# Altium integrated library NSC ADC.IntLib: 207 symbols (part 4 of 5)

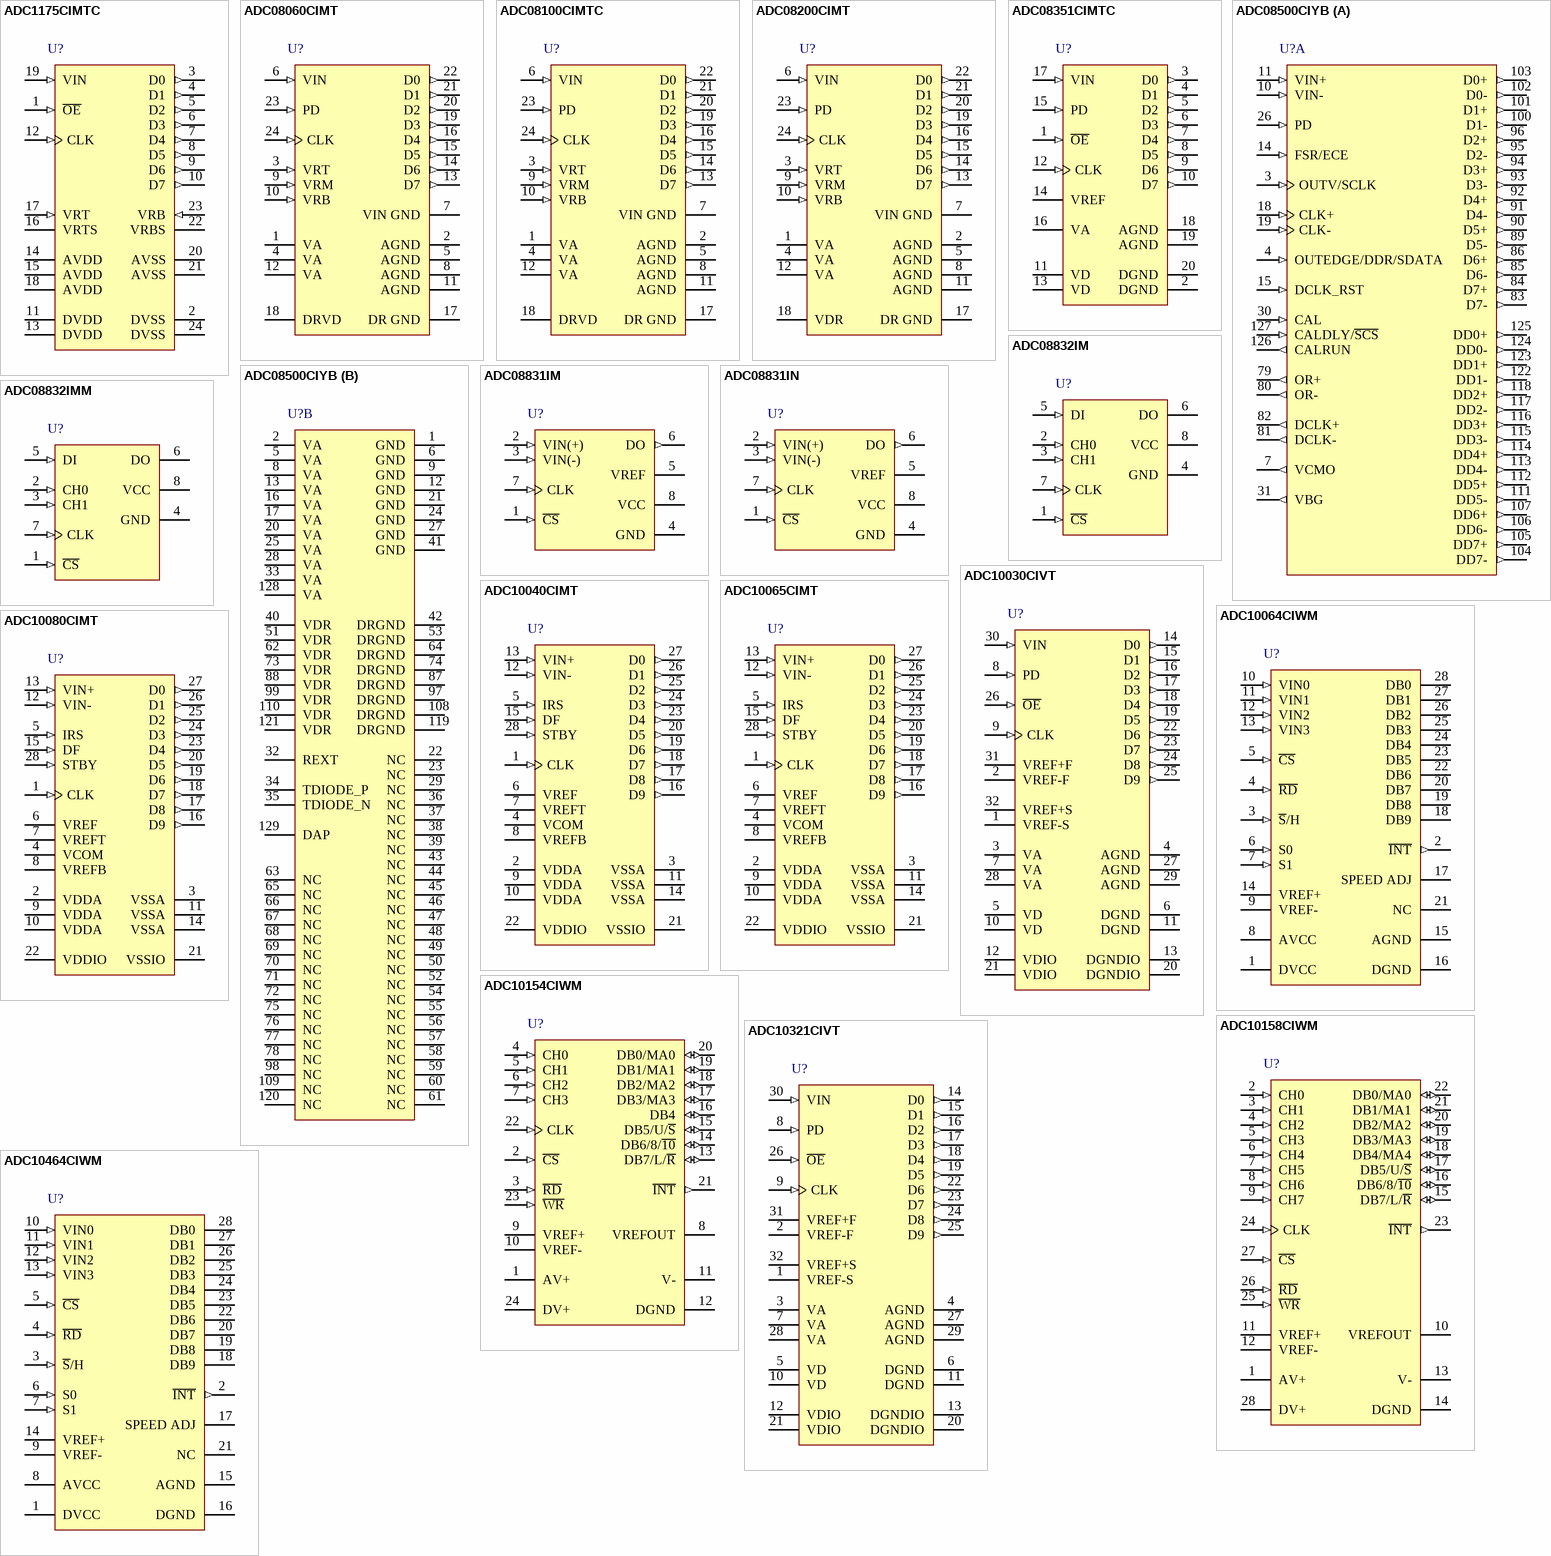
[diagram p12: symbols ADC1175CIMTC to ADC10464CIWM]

## ADC1175CIMTC
designator U?
8-Bit, 20MHz, 60mW A/D Converter; PartNumber: ADC1175CIMTC; Manufacturer: National Semiconductor; CompType: ADC IC; PackageTopMarking: NSUZXYTT*ADC1175*CIMTC; PowerWise: N
footprint MTC24_N (TSOP, 24-Leads, Body 7.8x4.4mm, Pitch 0.65mm, IPC Medium Density)
footprint MTC24_L (TSOP, 24-Leads, Body 7.8x4.4mm, Pitch 0.65mm, IPC High Density)
footprint MTC24_M (TSOP, 24-Leads, Body 7.8x4.4mm, Pitch 0.65mm, IPC Low Density)
pins: 1 ~{OE} (in), 2 DVSS (power), 3 D0 (out), 4 D1 (out), 5 D2 (out), 6 D3 (out), 7 D4 (out), 8 D5 (out), 9 D6 (out), 10 D7 (out), 11 DVDD (power), 12 CLK (in), 13 DVDD (power), 14 AVDD (power), 15 AVDD (power), 16 VRTS, 17 VRT (in), 18 AVDD (power), 19 VIN (in), 20 AVSS (power), 21 AVSS (power), 22 VRBS, 23 VRB (in), 24 DVSS (power)

## ADC08060CIMT
designator U?
8-Bit, 20 MSPS to 60 MSPS, 1.3 mW/MSPS A/D Converter with Internal Sample-and-Hold; PartNumber: ADC08060CIMT; Manufacturer: National Semiconductor; CompType: ADC IC; PackageTopMarking: NSUZXYTT*ADC08060*CIMT; PowerWise: N
footprint MTC24_N (TSOP, 24-Leads, Body 7.8x4.4mm, Pitch 0.65mm, IPC Medium Density)
footprint MTC24_L (TSOP, 24-Leads, Body 7.8x4.4mm, Pitch 0.65mm, IPC High Density)
footprint MTC24_M (TSOP, 24-Leads, Body 7.8x4.4mm, Pitch 0.65mm, IPC Low Density)
pins: 1 VA (power), 2 AGND (power), 3 VRT (in), 4 VA (power), 5 AGND (power), 6 VIN (in), 7 VIN GND (power), 8 AGND (power), 9 VRM (in), 10 VRB (in), 11 AGND (power), 12 VA (power), 13 D7 (out), 14 D6 (out), 15 D5 (out), 16 D4 (out), 17 DR GND (power), 18 DRVD (power), 19 D3 (out), 20 D2 (out), 21 D1 (out), 22 D0 (out), 23 PD (in), 24 CLK (in)

## ADC08100CIMTC
designator U?
8-Bit, 20 Msps to 100 Msps, 1.3 mW/Msps A/D Converter; PartNumber: ADC08100CIMTC; Manufacturer: National Semiconductor; CompType: ADC IC; PackageTopMarking: NSUZXYTT*ADC08100*CIMTC; PowerWise: N
footprint MTC24_N (TSOP, 24-Leads, Body 7.8x4.4mm, Pitch 0.65mm, IPC Medium Density)
footprint MTC24_L (TSOP, 24-Leads, Body 7.8x4.4mm, Pitch 0.65mm, IPC High Density)
footprint MTC24_M (TSOP, 24-Leads, Body 7.8x4.4mm, Pitch 0.65mm, IPC Low Density)
pins: 1 VA (power), 2 AGND (power), 3 VRT (in), 4 VA (power), 5 AGND (power), 6 VIN (in), 7 VIN GND (power), 8 AGND (power), 9 VRM (in), 10 VRB (in), 11 AGND (power), 12 VA (power), 13 D7 (out), 14 D6 (out), 15 D5 (out), 16 D4 (out), 17 DR GND (power), 18 DRVD (power), 19 D3 (out), 20 D2 (out), 21 D1 (out), 22 D0 (out), 23 PD (in), 24 CLK (in)

## ADC08200CIMT
designator U?
8-Bit, 20 Msps to 200 Msps, Low Power A/D Converter with Internal Sample-and-Hold; PartNumber: ADC08200CIMT; Manufacturer: National Semiconductor; CompType: ADC IC; PackageTopMarking: NSUZXYTT*ADC08200*CIMT; PowerWise: Y
footprint MTC24_N (TSOP, 24-Leads, Body 7.8x4.4mm, Pitch 0.65mm, IPC Medium Density)
footprint MTC24_L (TSOP, 24-Leads, Body 7.8x4.4mm, Pitch 0.65mm, IPC High Density)
footprint MTC24_M (TSOP, 24-Leads, Body 7.8x4.4mm, Pitch 0.65mm, IPC Low Density)
pins: 1 VA (power), 2 AGND (power), 3 VRT (in), 4 VA (power), 5 AGND (power), 6 VIN (in), 7 VIN GND (power), 8 AGND (power), 9 VRM (in), 10 VRB (in), 11 AGND (power), 12 VA (power), 13 D7 (out), 14 D6 (out), 15 D5 (out), 16 D4 (out), 17 DR GND (power), 18 VDR (power), 19 D3 (out), 20 D2 (out), 21 D1 (out), 22 D0 (out), 23 PD (in), 24 CLK (in)

## ADC08351CIMTC
designator U?
8-Bit, 42 MSPS, 40 mW A/D Converter; PartNumber: ADC08351CIMTC; Manufacturer: National Semiconductor; CompType: ADC IC; PackageTopMarking: NSUZXYTT*ADC08351*CIMTC
footprint MTC20_N (TSOP, 20-Leads, Body 6.5x4.4mm, Pitch 0.65mm, IPC Medium Density)
footprint MTC20_L (TSOP, 20-Leads, Body 6.5x4.4mm, Pitch 0.65mm, IPC High Density)
footprint MTC20_M (TSOP, 20-Leads, Body 6.5x4.4mm, Pitch 0.65mm, IPC Low Density)
pins: 1 ~{OE} (in), 2 DGND (power), 3 D0 (out), 4 D1 (out), 5 D2 (out), 6 D3 (out), 7 D4 (out), 8 D5 (out), 9 D6 (out), 10 D7 (out), 11 VD (power), 12 CLK (in), 13 VD (power), 14 VREF (power), 15 PD (in), 16 VA (power), 17 VIN (in), 18 AGND (power), 19 AGND (power), 20 DGND (power)

## ADC08500CIYB
designator U?
High Performance, Low Power, Dual 8-Bit, 500 MSPS A/D Converter; PartNumber: ADC08500CIYB; Manufacturer: National Semiconductor; CompType: ADC IC; PackageTopMarking: NSUZXYYTTE#*ADC08500CIYB; PowerWise: Y
footprint VNX128A_N (Thin QFP, 128-Leads, Body 20x20mm, Pitch 0.5mm, Exposed Pad, IPC Medium Density)
footprint VNX128A_L (Thin QFP, 128-Leads, Body 20x20mm, Pitch 0.5mm, Exposed Pad, IPC High Density)
footprint VNX128A_M (Thin QFP, 128-Leads, Body 20x20mm, Pitch 0.5mm, Exposed Pad, IPC Low Density)
part A pins: 3 OUTV/SCLK (in), 4 OUTEDGE/DDR/SDATA (in), 7 VCMO (out), 10 VIN- (in), 11 VIN+ (in), 14 FSR/ECE (in), 15 DCLK_RST (in), 18 CLK+ (in), 19 CLK- (in), 26 PD (in), 30 CAL (in), 31 VBG (out), 79 OR+ (out), 80 OR- (out), 81 DCLK- (out), 82 DCLK+ (out), 83 D7- (out), 84 D7+ (out), 85 D6- (out), 86 D6+ (out), 89 D5- (out), 90 D5+ (out), 91 D4- (out), 92 D4+ (out), 93 D3- (out), 94 D3+ (out), 95 D2- (out), 96 D2+ (out), 100 D1- (out), 101 D1+ (out), 102 D0- (out), 103 D0+ (out), 104 DD7- (out), 105 DD7+ (out), 106 DD6- (out), 107 DD6+ (out), 111 DD5- (out), 112 DD5+ (out), 113 DD4- (out), 114 DD4+ (out), 115 DD3- (out), 116 DD3+ (out), 117 DD2- (out), 118 DD2+ (out), 122 DD1- (out), 123 DD1+ (out), 124 DD0- (out), 125 DD0+ (out), 126 CALRUN (out), 127 CALDLY/~{SCS} (in)
part B pins: 1 GND (power), 2 VA (power), 5 VA (power), 6 GND (power), 8 VA (power), 9 GND (power), 12 GND (power), 13 VA (power), 16 VA (power), 17 VA (power), 20 VA (power), 21 GND (power), 22 NC, 23 NC, 24 GND (power), 25 VA (power), 27 GND (power), 28 VA (power), 29 NC, 32 REXT, 33 VA (power), 34 TDIODE_P, 35 TDIODE_N, 36 NC, 37 NC, 38 NC, 39 NC, 40 VDR (power), 41 GND (power), 42 DRGND (power), 43 NC, 44 NC, 45 NC, 46 NC, 47 NC, 48 NC, 49 NC, 50 NC, 51 VDR (power), 52 NC, 53 DRGND (power), 54 NC, 55 NC, 56 NC, 57 NC, 58 NC, 59 NC, 60 NC, 61 NC, 62 VDR (power), 63 NC, 64 DRGND (power), 65 NC, 66 NC, 67 NC, 68 NC, 69 NC, 70 NC, 71 NC, 72 NC, 73 VDR (power), 74 DRGND (power), 75 NC, 76 NC, 77 NC, 78 NC, 87 DRGND (power), 88 VDR (power), 97 DRGND (power), 98 NC, 99 VDR (power), 108 DRGND (power), 109 NC, 110 VDR (power), 119 DRGND (power), 120 NC, 121 VDR (power), 128 VA (power), 129 DAP (power)

## ADC08831IM
designator U?
8-Bit Serial I/O CMOS A/D Converters with Multiplexer and Sample/Hold Function; PartNumber: ADC08831IM; Manufacturer: National Semiconductor; CompType: ADC IC; PackageTopMarking: NSZXTT*08831*IM; PowerWise: N
footprint M08A_N (SOIC, 8-Leads, Body 4.9x3.9mm, Pitch 1.27mm, IPC Medium Density)
footprint M08A_L (SOIC, 8-Leads, Body 4.9x3.9mm, Pitch 1.27mm, IPC High Density)
footprint M08A_M (SOIC, 8-Leads, Body 4.9x3.9mm, Pitch 1.27mm, IPC Low Density)
pins: 1 ~{CS} (in), 2 VIN(+) (in), 3 VIN(-) (in), 4 GND (power), 5 VREF (power), 6 DO (out), 7 CLK (in), 8 VCC (power)

## ADC08831IN
designator U?
8-Bit Serial I/O CMOS A/D Converters with Multiplexer and Sample/Hold Function; PartNumber: ADC08831IN; Manufacturer: National Semiconductor; CompType: ADC IC; PackageTopMarking: NSUZXYTT*ADC08831*IN
footprint N08E (DIP, 8-Leads, Row Spacing 7.62mm, Pitch 2.54mm, Body 9.91x6.35mm)
pins: 1 ~{CS} (in), 2 VIN(+) (in), 3 VIN(-) (in), 4 GND (power), 5 VREF (power), 6 DO (out), 7 CLK (in), 8 VCC (power)

## ADC08832IM
designator U?
8-Bit Serial I/O CMOS A/D Converters with Multiplexer and Sample/Hold Function; PartNumber: ADC08832IM; Manufacturer: National Semiconductor; CompType: ADC IC; PackageTopMarking: NSZXTT*08832*IM; PowerWise: N
footprint M08A_N (SOIC, 8-Leads, Body 4.9x3.9mm, Pitch 1.27mm, IPC Medium Density)
footprint M08A_L (SOIC, 8-Leads, Body 4.9x3.9mm, Pitch 1.27mm, IPC High Density)
footprint M08A_M (SOIC, 8-Leads, Body 4.9x3.9mm, Pitch 1.27mm, IPC Low Density)
pins: 1 ~{CS} (in), 2 CH0 (in), 3 CH1 (in), 4 GND (power), 5 DI (in), 6 DO (hiz), 7 CLK (in), 8 VCC (power)

## ADC08832IMM
designator U?
8-Bit Serial I/O CMOS A/D Converters with Multiplexer and Sample/Hold Function; PartNumber: ADC08832IMM; Manufacturer: National Semiconductor; CompType: ADC IC; PackageTopMarking: ZXTT*8832; PowerWise: N
footprint MUA08A_N (TSOP, 8-Leads, Body 3x3mm, Pitch 0.65mm, IPC Medium Density)
footprint MUA08A_L (TSOP, 8-Leads, Body 3x3mm, Pitch 0.65mm, IPC High Density)
footprint MUA08A_M (TSOP, 8-Leads, Body 3x3mm, Pitch 0.65mm, IPC Low Density)
pins: 1 ~{CS} (in), 2 CH0 (in), 3 CH1 (in), 4 GND (power), 5 DI (in), 6 DO (hiz), 7 CLK (in), 8 VCC (power)

## ADC10030CIVT
designator U?
10-Bit, 30 MSPS, 125 mW A/D Converter with Internal Sample and Hold; PartNumber: ADC10030CIVT; Manufacturer: National Semiconductor; CompType: ADC IC; PackageTopMarking: NS2ZXYTT*ADC10030*CIVT
footprint VBE32A_N (Thin QFP, 32-Leads, Body 7x7mm, Pitch 0.8mm, IPC Medium Density)
footprint VBE32A_L (Thin QFP, 32-Leads, Body 7x7mm, Pitch 0.8mm, IPC High Density)
footprint VBE32A_M (Thin QFP, 32-Leads, Body 7x7mm, Pitch 0.8mm, IPC Low Density)
pins: 1 VREF-S (power), 2 VREF-F (power), 3 VA (power), 4 AGND (power), 5 VD (power), 6 DGND (power), 7 VA (power), 8 PD (in), 9 CLK (in), 10 VD (power), 11 DGND (power), 12 VDIO (power), 13 DGNDIO (power), 14 D0 (out), 15 D1 (out), 16 D2 (out), 17 D3 (out), 18 D4 (out), 19 D5 (out), 20 DGNDIO (power), 21 VDIO (power), 22 D6 (out), 23 D7 (out), 24 D8 (out), 25 D9 (out), 26 ~{OE} (in), 27 AGND (power), 28 VA (power), 29 AGND (power), 30 VIN (in), 31 VREF+F (power), 32 VREF+S (power)

## ADC10040CIMT
designator U?
10-Bit, 40 MSPS, 3V, 55.5 mW A/D Converter; PartNumber: ADC10040CIMT; Manufacturer: National Semiconductor; CompType: ADC IC; PackageTopMarking: NSUZXYTT*ADC10040*CIMT; PowerWise: Y
footprint MTC28_N (TSOP, 28-Leads, Body 9.7x4.4mm, Pitch 0.65mm, IPC Medium Density)
footprint MTC28_L (TSOP, 28-Leads, Body 9.7x4.4mm, Pitch 0.65mm, IPC High Density)
footprint MTC28_M (TSOP, 28-Leads, Body 9.7x4.4mm, Pitch 0.65mm, IPC Low Density)
pins: 1 CLK (in), 2 VDDA (power), 3 VSSA (power), 4 VCOM (power), 5 IRS (in), 6 VREF (power), 7 VREFT (power), 8 VREFB (power), 9 VDDA (power), 10 VDDA (power), 11 VSSA (power), 12 VIN- (in), 13 VIN+ (in), 14 VSSA (power), 15 DF (in), 16 D9 (out), 17 D8 (out), 18 D7 (out), 19 D6 (out), 20 D5 (out), 21 VSSIO (power), 22 VDDIO (power), 23 D4 (out), 24 D3 (out), 25 D2 (out), 26 D1 (out), 27 D0 (out), 28 STBY (in)

## ADC10064CIWM
designator U?
10-Bit 600 ns A/D Converter with Input Multiplexer and Sample/Hold; PartNumber: ADC10064CIWM; Manufacturer: National Semiconductor; CompType: ADC IC; PackageTopMarking: NSUZXYTT*ADC10064*CIWM; PowerWise: N
footprint M28B_N (SOIC, 28-Leads, Body 17.9x7.5mm, Pitch 1.27mm, IPC Medium Density)
footprint M28B_L (SOIC, 28-Leads, Body 17.9x7.5mm, Pitch 1.27mm, IPC High Density)
footprint M28B_M (SOIC, 28-Leads, Body 17.9x7.5mm, Pitch 1.27mm, IPC Low Density)
pins: 1 DVCC (power), 2 ~{INT} (out), 3 ~{S}/H (in), 4 ~{RD} (in), 5 ~{CS} (in), 6 S0 (in), 7 S1 (in), 8 AVCC (power), 9 VREF- (power), 10 VIN0 (in), 11 VIN1 (in), 12 VIN2 (in), 13 VIN3 (in), 14 VREF+ (power), 15 AGND (power), 16 DGND (power), 17 SPEED ADJ, 18 DB9 (hiz), 19 DB8 (hiz), 20 DB7 (hiz), 21 NC, 22 DB6 (hiz), 23 DB5 (hiz), 24 DB4 (hiz), 25 DB3 (hiz), 26 DB2 (hiz), 27 DB1 (hiz), 28 DB0 (hiz)

## ADC10065CIMT
designator U?
10-Bit 65 MSPS 3V A/D Converter; PartNumber: ADC10065CIMT; Manufacturer: National Semiconductor; CompType: ADC IC; PackageTopMarking: NSUZXYTT*ADC10065*CIMT; PowerWise: Y
footprint MTC28_N (TSOP, 28-Leads, Body 9.7x4.4mm, Pitch 0.65mm, IPC Medium Density)
footprint MTC28_L (TSOP, 28-Leads, Body 9.7x4.4mm, Pitch 0.65mm, IPC High Density)
footprint MTC28_M (TSOP, 28-Leads, Body 9.7x4.4mm, Pitch 0.65mm, IPC Low Density)
pins: 1 CLK (in), 2 VDDA (power), 3 VSSA (power), 4 VCOM (power), 5 IRS (in), 6 VREF (power), 7 VREFT (power), 8 VREFB (power), 9 VDDA (power), 10 VDDA (power), 11 VSSA (power), 12 VIN- (in), 13 VIN+ (in), 14 VSSA (power), 15 DF (in), 16 D9 (out), 17 D8 (out), 18 D7 (out), 19 D6 (out), 20 D5 (out), 21 VSSIO (power), 22 VDDIO (power), 23 D4 (out), 24 D3 (out), 25 D2 (out), 26 D1 (out), 27 D0 (out), 28 STBY (in)

## ADC10080CIMT
designator U?
10-Bit, 80 MSPS, 3V, 78.6 mW A/D Converter; PartNumber: ADC10080CIMT; Manufacturer: National Semiconductor; CompType: ADC IC; PackageTopMarking: NSUZXYTT*ADC10080*CIMT; PowerWise: Y
footprint MTC28_N (TSOP, 28-Leads, Body 9.7x4.4mm, Pitch 0.65mm, IPC Medium Density)
footprint MTC28_L (TSOP, 28-Leads, Body 9.7x4.4mm, Pitch 0.65mm, IPC High Density)
footprint MTC28_M (TSOP, 28-Leads, Body 9.7x4.4mm, Pitch 0.65mm, IPC Low Density)
pins: 1 CLK (in), 2 VDDA (power), 3 VSSA (power), 4 VCOM (power), 5 IRS (in), 6 VREF (power), 7 VREFT (power), 8 VREFB (power), 9 VDDA (power), 10 VDDA (power), 11 VSSA (power), 12 VIN- (in), 13 VIN+ (in), 14 VSSA (power), 15 DF (in), 16 D9 (out), 17 D8 (out), 18 D7 (out), 19 D6 (out), 20 D5 (out), 21 VSSIO (power), 22 VDDIO (power), 23 D4 (out), 24 D3 (out), 25 D2 (out), 26 D1 (out), 27 D0 (out), 28 STBY (in)

## ADC10154CIWM
designator U?
10-Bit Plus Sign 4 microseconds ADCs with 4- or 8-Channel MUX, Track/Hold and Reference; PartNumber: ADC10154CIWM; Manufacturer: National Semiconductor; CompType: ADC IC; PackageTopMarking: NSUZXYTT*ADC10154*CIWM; PowerWise: N
footprint M24B_N (SOIC, 24-Leads, Body 15.4x7.5mm, Pitch 1.27mm, IPC Medium Density)
footprint M24B_L (SOIC, 24-Leads, Body 15.4x7.5mm, Pitch 1.27mm, IPC High Density)
footprint M24B_M (SOIC, 24-Leads, Body 15.4x7.5mm, Pitch 1.27mm, IPC Low Density)
pins: 1 AV+ (power), 2 ~{CS} (in), 3 ~{RD} (in), 4 CH0 (in), 5 CH1 (in), 6 CH2 (in), 7 CH3 (in), 8 VREFOUT (power), 9 VREF+ (power), 10 VREF- (power), 11 V- (power), 12 DGND (power), 13 DB7/L/~{R} (io), 14 DB6/8/~{10} (io), 15 DB5/U/~{S} (io), 16 DB4 (io), 17 DB3/MA3 (io), 18 DB2/MA2 (io), 19 DB1/MA1 (io), 20 DB0/MA0 (io), 21 ~{INT} (out), 22 CLK (in), 23 ~{WR} (in), 24 DV+ (power)

## ADC10158CIWM
designator U?
10-Bit Plus Sign 4 microseconds ADCs with 4- or 8-Channel MUX, Track/Hold and Reference; PartNumber: ADC10158CIWM; Manufacturer: National Semiconductor; CompType: ADC IC; PackageTopMarking: NSUZXYTT*ADC10158*CIWM; PowerWise: N
footprint M28B_N (SOIC, 28-Leads, Body 17.9x7.5mm, Pitch 1.27mm, IPC Medium Density)
footprint M28B_L (SOIC, 28-Leads, Body 17.9x7.5mm, Pitch 1.27mm, IPC High Density)
footprint M28B_M (SOIC, 28-Leads, Body 17.9x7.5mm, Pitch 1.27mm, IPC Low Density)
pins: 1 AV+ (power), 2 CH0 (in), 3 CH1 (in), 4 CH2 (in), 5 CH3 (in), 6 CH4 (in), 7 CH5 (in), 8 CH6 (in), 9 CH7 (in), 10 VREFOUT (power), 11 VREF+ (power), 12 VREF- (power), 13 V- (power), 14 DGND (power), 15 DB7/L/~{R} (io), 16 DB6/8/~{10} (io), 17 DB5/U/~{S} (io), 18 DB4/MA4 (io), 19 DB3/MA3 (io), 20 DB2/MA2 (io), 21 DB1/MA1 (io), 22 DB0/MA0 (io), 23 ~{INT} (out), 24 CLK (in), 25 ~{WR} (in), 26 ~{RD} (in), 27 ~{CS} (in), 28 DV+ (power)

## ADC10321CIVT
designator U?
10-Bit, 20MSPS, 98mW A/D Converter with Internal Sample and Hold; PartNumber: ADC10321CIVT; Manufacturer: National Semiconductor; CompType: ADC IC; PackageTopMarking: NS2ZXYTT*ADC10321*CIVT; PowerWise: N
footprint VBE32A_N (Thin QFP, 32-Leads, Body 7x7mm, Pitch 0.8mm, IPC Medium Density)
footprint VBE32A_L (Thin QFP, 32-Leads, Body 7x7mm, Pitch 0.8mm, IPC High Density)
footprint VBE32A_M (Thin QFP, 32-Leads, Body 7x7mm, Pitch 0.8mm, IPC Low Density)
pins: 1 VREF-S (power), 2 VREF-F (power), 3 VA (power), 4 AGND (power), 5 VD (power), 6 DGND (power), 7 VA (power), 8 PD (in), 9 CLK (in), 10 VD (power), 11 DGND (power), 12 VDIO (power), 13 DGNDIO (power), 14 D0 (out), 15 D1 (out), 16 D2 (out), 17 D3 (out), 18 D4 (out), 19 D5 (out), 20 DGNDIO (power), 21 VDIO (power), 22 D6 (out), 23 D7 (out), 24 D8 (out), 25 D9 (out), 26 ~{OE} (in), 27 AGND (power), 28 VA (power), 29 AGND (power), 30 VIN (in), 31 VREF+F (power), 32 VREF+S (power)

## ADC10464CIWM
designator U?
10-Bit 600 ns A/D Converter with Input Multiplexer and Sample/Hold; PartNumber: ADC10464CIWM; Manufacturer: National Semiconductor; CompType: ADC IC; PackageTopMarking: NSUZXYTT*ADC10464*CIWM; PowerWise: N
footprint M28B_N (SOIC, 28-Leads, Body 17.9x7.5mm, Pitch 1.27mm, IPC Medium Density)
footprint M28B_L (SOIC, 28-Leads, Body 17.9x7.5mm, Pitch 1.27mm, IPC High Density)
footprint M28B_M (SOIC, 28-Leads, Body 17.9x7.5mm, Pitch 1.27mm, IPC Low Density)
pins: 1 DVCC (power), 2 ~{INT} (out), 3 ~{S}/H (in), 4 ~{RD} (in), 5 ~{CS} (in), 6 S0 (in), 7 S1 (in), 8 AVCC (power), 9 VREF- (power), 10 VIN0 (in), 11 VIN1 (in), 12 VIN2 (in), 13 VIN3 (in), 14 VREF+ (power), 15 AGND (power), 16 DGND (power), 17 SPEED ADJ, 18 DB9 (hiz), 19 DB8 (hiz), 20 DB7 (hiz), 21 NC, 22 DB6 (hiz), 23 DB5 (hiz), 24 DB4 (hiz), 25 DB3 (hiz), 26 DB2 (hiz), 27 DB1 (hiz), 28 DB0 (hiz)

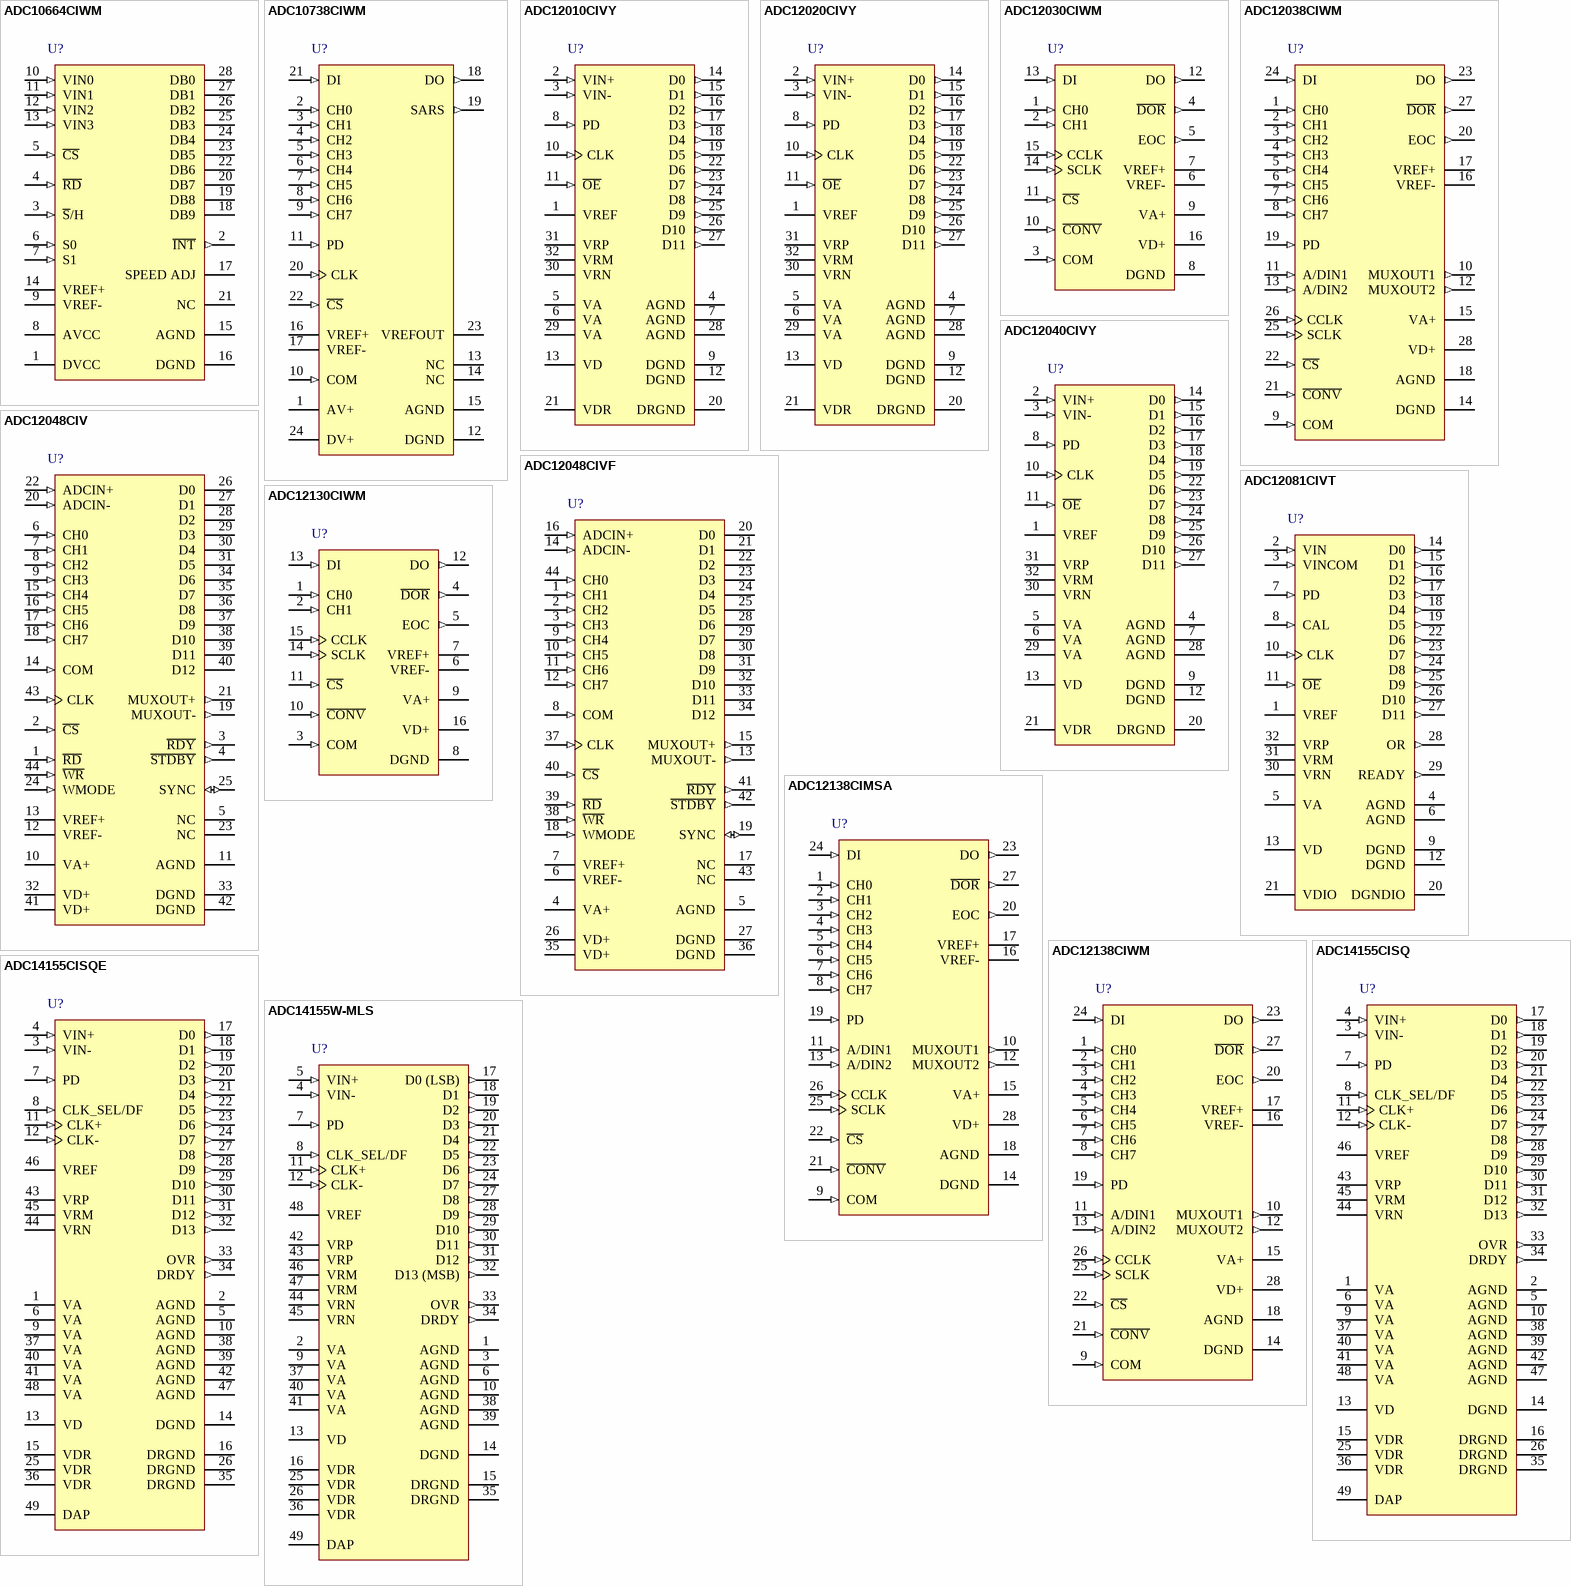
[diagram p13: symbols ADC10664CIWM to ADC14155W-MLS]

## ADC10664CIWM
designator U?
10-Bit 360 ns A/D Converter with Input Multiplexer and Sample/Hold; PartNumber: ADC10664CIWM; Manufacturer: National Semiconductor; CompType: ADC IC; PackageTopMarking: NSUZXYTT*ADC10664*CIWM; PowerWise: N
footprint M28B_N (SOIC, 28-Leads, Body 17.9x7.5mm, Pitch 1.27mm, IPC Medium Density)
footprint M28B_L (SOIC, 28-Leads, Body 17.9x7.5mm, Pitch 1.27mm, IPC High Density)
footprint M28B_M (SOIC, 28-Leads, Body 17.9x7.5mm, Pitch 1.27mm, IPC Low Density)
pins: 1 DVCC (power), 2 ~{INT} (out), 3 ~{S}/H (in), 4 ~{RD} (in), 5 ~{CS} (in), 6 S0 (in), 7 S1 (in), 8 AVCC (power), 9 VREF- (power), 10 VIN0 (in), 11 VIN1 (in), 12 VIN2 (in), 13 VIN3 (in), 14 VREF+ (power), 15 AGND (power), 16 DGND (power), 17 SPEED ADJ, 18 DB9 (hiz), 19 DB8 (hiz), 20 DB7 (hiz), 21 NC, 22 DB6 (hiz), 23 DB5 (hiz), 24 DB4 (hiz), 25 DB3 (hiz), 26 DB2 (hiz), 27 DB1 (hiz), 28 DB0 (hiz)

## ADC10738CIWM
designator U?
10-Bit Plus Sign Serial I/O A/D Converters with Mux, Sample/Hold and Reference; PartNumber: ADC10738CIWM; Manufacturer: National Semiconductor; CompType: ADC IC; PackageTopMarking: NSUZXYTT*ADC10738*CIWM; PowerWise: N
footprint M24B_N (SOIC, 24-Leads, Body 15.4x7.5mm, Pitch 1.27mm, IPC Medium Density)
footprint M24B_L (SOIC, 24-Leads, Body 15.4x7.5mm, Pitch 1.27mm, IPC High Density)
footprint M24B_M (SOIC, 24-Leads, Body 15.4x7.5mm, Pitch 1.27mm, IPC Low Density)
pins: 1 AV+ (power), 2 CH0 (in), 3 CH1 (in), 4 CH2 (in), 5 CH3 (in), 6 CH4 (in), 7 CH5 (in), 8 CH6 (in), 9 CH7 (in), 10 COM (in), 11 PD (in), 12 DGND (power), 13 NC, 14 NC, 15 AGND (power), 16 VREF+ (power), 17 VREF- (power), 18 DO (out), 19 SARS (out), 20 CLK (in), 21 DI (in), 22 ~{CS} (in), 23 VREFOUT (power), 24 DV+ (power)

## ADC12010CIVY
designator U?
12-Bit, 10 MSPS, 160 mW A/D Converter with Internal Sample-and-Hold; PartNumber: ADC12010CIVY; Manufacturer: National Semiconductor; CompType: ADC IC; PackageTopMarking: NSUZXYTT*ADC12010*CIVY; PowerWise: N
footprint VBE32A_N (Thin QFP, 32-Leads, Body 7x7mm, Pitch 0.8mm, IPC Medium Density)
footprint VBE32A_L (Thin QFP, 32-Leads, Body 7x7mm, Pitch 0.8mm, IPC High Density)
footprint VBE32A_M (Thin QFP, 32-Leads, Body 7x7mm, Pitch 0.8mm, IPC Low Density)
pins: 1 VREF (power), 2 VIN+ (in), 3 VIN- (in), 4 AGND (power), 5 VA (power), 6 VA (power), 7 AGND (power), 8 PD (in), 9 DGND (power), 10 CLK (in), 11 ~{OE} (in), 12 DGND (power), 13 VD (power), 14 D0 (out), 15 D1 (out), 16 D2 (out), 17 D3 (out), 18 D4 (out), 19 D5 (out), 20 DRGND (power), 21 VDR (power), 22 D6 (out), 23 D7 (out), 24 D8 (out), 25 D9 (out), 26 D10 (out), 27 D11 (out), 28 AGND (power), 29 VA (power), 30 VRN, 31 VRP, 32 VRM

## ADC12020CIVY
designator U?
12-Bit, 20 MSPS, 185mW A/D Converter with Internal Sample-and-Hold; PartNumber: ADC12020CIVY; Manufacturer: National Semiconductor; CompType: ADC IC; PackageTopMarking: NSUZXYTT*ADC12020*CIVY; PowerWise: N
footprint VBE32A_N (Thin QFP, 32-Leads, Body 7x7mm, Pitch 0.8mm, IPC Medium Density)
footprint VBE32A_L (Thin QFP, 32-Leads, Body 7x7mm, Pitch 0.8mm, IPC High Density)
footprint VBE32A_M (Thin QFP, 32-Leads, Body 7x7mm, Pitch 0.8mm, IPC Low Density)
pins: 1 VREF (power), 2 VIN+ (in), 3 VIN- (in), 4 AGND (power), 5 VA (power), 6 VA (power), 7 AGND (power), 8 PD (in), 9 DGND (power), 10 CLK (in), 11 ~{OE} (in), 12 DGND (power), 13 VD (power), 14 D0 (out), 15 D1 (out), 16 D2 (out), 17 D3 (out), 18 D4 (out), 19 D5 (out), 20 DRGND (power), 21 VDR (power), 22 D6 (out), 23 D7 (out), 24 D8 (out), 25 D9 (out), 26 D10 (out), 27 D11 (out), 28 AGND (power), 29 VA (power), 30 VRN, 31 VRP, 32 VRM

## ADC12030CIWM
designator U?
Self-Calibrating 12-Bit Plus Sign Serial I/O A/D Converters with MUX and Sample/Hold; PartNumber: ADC12030CIWM; Manufacturer: National Semiconductor; CompType: ADC IC; PackageTopMarking: NSUZXYTT*ADC12030*CIWM; PowerWise: N
footprint M16B_N (SOIC, 16-Leads, Body 10.3x7.5mm, Pitch 1.27mm, IPC Medium Density)
footprint M16B_L (SOIC, 16-Leads, Body 10.3x7.5mm, Pitch 1.27mm, IPC High Density)
footprint M16B_M (SOIC, 16-Leads, Body 10.3x7.5mm, Pitch 1.27mm, IPC Low Density)
pins: 1 CH0 (in), 2 CH1 (in), 3 COM (in), 4 ~{DOR} (out), 5 EOC (out), 6 VREF- (power), 7 VREF+ (power), 8 DGND (power), 9 VA+ (power), 10 ~{CONV} (in), 11 ~{CS} (in), 12 DO (out), 13 DI (in), 14 SCLK (in), 15 CCLK (in), 16 VD+ (power)

## ADC12038CIWM
designator U?
Self-Calibrating 12-Bit Plus Sign Serial I/O A/D Converters with MUX and Sample/Hold; PartNumber: ADC12038CIWM; Manufacturer: National Semiconductor; CompType: ADC IC; PackageTopMarking: NSUZXYTT*ADC12038*CIWM; PowerWise: N
footprint M28B_N (SOIC, 28-Leads, Body 17.9x7.5mm, Pitch 1.27mm, IPC Medium Density)
footprint M28B_L (SOIC, 28-Leads, Body 17.9x7.5mm, Pitch 1.27mm, IPC High Density)
footprint M28B_M (SOIC, 28-Leads, Body 17.9x7.5mm, Pitch 1.27mm, IPC Low Density)
pins: 1 CH0 (in), 2 CH1 (in), 3 CH2 (in), 4 CH3 (in), 5 CH4 (in), 6 CH5 (in), 7 CH6 (in), 8 CH7 (in), 9 COM (in), 10 MUXOUT1 (out), 11 A/DIN1 (in), 12 MUXOUT2 (out), 13 A/DIN2 (in), 14 DGND (power), 15 VA+ (power), 16 VREF- (power), 17 VREF+ (power), 18 AGND (power), 19 PD (in), 20 EOC (out), 21 ~{CONV} (in), 22 ~{CS} (in), 23 DO (out), 24 DI (in), 25 SCLK (in), 26 CCLK (in), 27 ~{DOR} (out), 28 VD+ (power)

## ADC12040CIVY
designator U?
12-Bit, 40 MSPS, 340mW A/D Converter with Internal Sample-and-Hold; PartNumber: ADC12040CIVY; Manufacturer: National Semiconductor; CompType: ADC IC; PackageTopMarking: NSUZXYTT*ADC12040*CIVY; PowerWise: N
footprint VBE32A_N (Thin QFP, 32-Leads, Body 7x7mm, Pitch 0.8mm, IPC Medium Density)
footprint VBE32A_L (Thin QFP, 32-Leads, Body 7x7mm, Pitch 0.8mm, IPC High Density)
footprint VBE32A_M (Thin QFP, 32-Leads, Body 7x7mm, Pitch 0.8mm, IPC Low Density)
pins: 1 VREF (power), 2 VIN+ (in), 3 VIN- (in), 4 AGND (power), 5 VA (power), 6 VA (power), 7 AGND (power), 8 PD (in), 9 DGND (power), 10 CLK (in), 11 ~{OE} (in), 12 DGND (power), 13 VD (power), 14 D0 (out), 15 D1 (out), 16 D2 (out), 17 D3 (out), 18 D4 (out), 19 D5 (out), 20 DRGND (power), 21 VDR (power), 22 D6 (out), 23 D7 (out), 24 D8 (out), 25 D9 (out), 26 D10 (out), 27 D11 (out), 28 AGND (power), 29 VA (power), 30 VRN, 31 VRP, 32 VRM

## ADC12048CIV
designator U?
12-Bit Plus Sign 216 kHz 8 Channel Sampling Analog to Digital Converter; PartNumber: ADC12048CIV; Manufacturer: National Semiconductor; CompType: ADC IC; PackageTopMarking: NSUZXYYTTE#*ADC12048CIV; PowerWise: N
footprint V44A_N (Leaded Chip Carrier, 44-Leads, Body 16.6x16.6mm, Pitch 1.27mm, IPC Medium Density)
footprint V44A_L (Leaded Chip Carrier, 44-Leads, Body 16.6x16.6mm, Pitch 1.27mm, IPC High Density)
footprint V44A_M (Leaded Chip Carrier, 44-Leads, Body 16.6x16.6mm, Pitch 1.27mm, IPC Low Density)
pins: 1 ~{RD} (in), 2 ~{CS} (in), 3 ~{RDY} (out), 4 ~{STDBY} (out), 5 NC, 6 CH0 (in), 7 CH1 (in), 8 CH2 (in), 9 CH3 (in), 10 VA+ (power), 11 AGND (power), 12 VREF- (power), 13 VREF+ (power), 14 COM (in), 15 CH4 (in), 16 CH5 (in), 17 CH6 (in), 18 CH7 (in), 19 MUXOUT- (out), 20 ADCIN- (in), 21 MUXOUT+ (out), 22 ADCIN+ (in), 23 NC, 24 WMODE (in), 25 SYNC (io), 26 D0 (hiz), 27 D1 (hiz), 28 D2 (hiz), 29 D3 (hiz), 30 D4 (hiz), 31 D5 (hiz), 32 VD+ (power), 33 DGND (power), 34 D6 (hiz), 35 D7 (hiz), 36 D8 (hiz), 37 D9 (hiz), 38 D10 (hiz), 39 D11 (hiz), 40 D12 (hiz), 41 VD+ (power), 42 DGND (power), 43 CLK (in), 44 ~{WR} (in)

## ADC12048CIVF
designator U?
12-Bit Plus Sign 216 kHz 8 Channel Sampling Analog to Digital Converter; PartNumber: ADC12048CIVF; Manufacturer: National Semiconductor; CompType: ADC IC; PackageTopMarking: NSUZXYYTT*ADC12048*CIVF*DIE RUN# =; PowerWise: N
footprint VGZ44A_N (QFP, 44-Leads, Body 10x10mm, Pitch 0.8mm, IPC Medium Density)
footprint VGZ44A_L (QFP, 44-Leads, Body 10x10mm, Pitch 0.8mm, IPC High Density)
footprint VGZ44A_M (QFP, 44-Leads, Body 10x10mm, Pitch 0.8mm, IPC Low Density)
pins: 1 CH1 (in), 2 CH2 (in), 3 CH3 (in), 4 VA+ (power), 5 AGND (power), 6 VREF- (power), 7 VREF+ (power), 8 COM (in), 9 CH4 (in), 10 CH5 (in), 11 CH6 (in), 12 CH7 (in), 13 MUXOUT- (out), 14 ADCIN- (in), 15 MUXOUT+ (out), 16 ADCIN+ (in), 17 NC, 18 WMODE (in), 19 SYNC (io), 20 D0 (hiz), 21 D1 (hiz), 22 D2 (hiz), 23 D3 (hiz), 24 D4 (hiz), 25 D5 (hiz), 26 VD+ (power), 27 DGND (power), 28 D6 (hiz), 29 D7 (hiz), 30 D8 (hiz), 31 D9 (hiz), 32 D10 (hiz), 33 D11 (hiz), 34 D12 (hiz), 35 VD+ (power), 36 DGND (power), 37 CLK (in), 38 ~{WR} (in), 39 ~{RD} (in), 40 ~{CS} (in), 41 ~{RDY} (out), 42 ~{STDBY} (out), 43 NC, 44 CH0 (in)

## ADC12081CIVT
designator U?
12-Bit, 5 MHz Self-Calibrating, Pipelined A/D Converter with Internal Sample &amp; Hold; PartNumber: ADC12081CIVT; Manufacturer: National Semiconductor; CompType: ADC IC; PackageTopMarking: NSUZXYTT*ADC12081*CIVT; PowerWise: N
footprint VBE32A_N (Thin QFP, 32-Leads, Body 7x7mm, Pitch 0.8mm, IPC Medium Density)
footprint VBE32A_L (Thin QFP, 32-Leads, Body 7x7mm, Pitch 0.8mm, IPC High Density)
footprint VBE32A_M (Thin QFP, 32-Leads, Body 7x7mm, Pitch 0.8mm, IPC Low Density)
pins: 1 VREF (power), 2 VIN (in), 3 VINCOM (in), 4 AGND (power), 5 VA (power), 6 AGND (power), 7 PD (in), 8 CAL (in), 9 DGND (power), 10 CLK (in), 11 ~{OE} (in), 12 DGND (power), 13 VD (power), 14 D0 (out), 15 D1 (out), 16 D2 (out), 17 D3 (out), 18 D4 (out), 19 D5 (out), 20 DGNDIO (power), 21 VDIO (power), 22 D6 (out), 23 D7 (out), 24 D8 (out), 25 D9 (out), 26 D10 (out), 27 D11 (out), 28 OR (out), 29 READY (out), 30 VRN, 31 VRM, 32 VRP

## ADC12130CIWM
designator U?
Self-Calibrating 12-Bit Plus Sign Serial I/O A/D Converter with MUX and Sample/Hold; PartNumber: ADC12130CIWM; Manufacturer: National Semiconductor; CompType: ADC IC; PackageTopMarking: NSUZXYTT*ADC12130*CIWM; PowerWise: N
footprint M16B_N (SOIC, 16-Leads, Body 10.3x7.5mm, Pitch 1.27mm, IPC Medium Density)
footprint M16B_L (SOIC, 16-Leads, Body 10.3x7.5mm, Pitch 1.27mm, IPC High Density)
footprint M16B_M (SOIC, 16-Leads, Body 10.3x7.5mm, Pitch 1.27mm, IPC Low Density)
pins: 1 CH0 (in), 2 CH1 (in), 3 COM (in), 4 ~{DOR} (out), 5 EOC (out), 6 VREF- (power), 7 VREF+ (power), 8 DGND (power), 9 VA+ (power), 10 ~{CONV} (in), 11 ~{CS} (in), 12 DO (out), 13 DI (in), 14 SCLK (in), 15 CCLK (in), 16 VD+ (power)

## ADC12138CIMSA
designator U?
Self-Calibrating 12-Bit Plus Sign Serial I/O A/D Converter with MUX and Sample/Hold; PartNumber: ADC12138CIMSA; Manufacturer: National Semiconductor; CompType: ADC IC; PackageTopMarking: NSUZXYTT*ADC12138*CIMSA; PowerWise: N
footprint MSA28_N (SOP, 28-Leads, Body 10.2x5.3mm, Pitch 0.65mm, IPC Medium Density)
footprint MSA28_L (SOP, 28-Leads, Body 10.2x5.3mm, Pitch 0.65mm, IPC High Density)
footprint MSA28_M (SOP, 28-Leads, Body 10.2x5.3mm, Pitch 0.65mm, IPC Low Density)
pins: 1 CH0 (in), 2 CH1 (in), 3 CH2 (in), 4 CH3 (in), 5 CH4 (in), 6 CH5 (in), 7 CH6 (in), 8 CH7 (in), 9 COM (in), 10 MUXOUT1 (out), 11 A/DIN1 (in), 12 MUXOUT2 (out), 13 A/DIN2 (in), 14 DGND (power), 15 VA+ (power), 16 VREF- (power), 17 VREF+ (power), 18 AGND (power), 19 PD (in), 20 EOC (out), 21 ~{CONV} (in), 22 ~{CS} (in), 23 DO (out), 24 DI (in), 25 SCLK (in), 26 CCLK (in), 27 ~{DOR} (out), 28 VD+ (power)

## ADC12138CIWM
designator U?
Self-Calibrating 12-Bit Plus Sign Serial I/O A/D Converter with MUX and Sample/Hold; PartNumber: ADC12138CIWM; Manufacturer: National Semiconductor; CompType: ADC IC; PackageTopMarking: NSUZXYTT*ADC12138*CIWM; PowerWise: N
footprint M28B_N (SOIC, 28-Leads, Body 17.9x7.5mm, Pitch 1.27mm, IPC Medium Density)
footprint M28B_L (SOIC, 28-Leads, Body 17.9x7.5mm, Pitch 1.27mm, IPC High Density)
footprint M28B_M (SOIC, 28-Leads, Body 17.9x7.5mm, Pitch 1.27mm, IPC Low Density)
pins: 1 CH0 (in), 2 CH1 (in), 3 CH2 (in), 4 CH3 (in), 5 CH4 (in), 6 CH5 (in), 7 CH6 (in), 8 CH7 (in), 9 COM (in), 10 MUXOUT1 (out), 11 A/DIN1 (in), 12 MUXOUT2 (out), 13 A/DIN2 (in), 14 DGND (power), 15 VA+ (power), 16 VREF- (power), 17 VREF+ (power), 18 AGND (power), 19 PD (in), 20 EOC (out), 21 ~{CONV} (in), 22 ~{CS} (in), 23 DO (out), 24 DI (in), 25 SCLK (in), 26 CCLK (in), 27 ~{DOR} (out), 28 VD+ (power)

## ADC14155CISQ
designator U?
14-Bit, 155 MSPS, 1.1 GHz Bandwidth A/D Converter; PartNumber: ADC14155CISQ; Manufacturer: National Semiconductor; CompType: ADC IC; PackageTopMarking: NS*UZXYTT*14155SQ; PowerWise: Y
footprint SQA48A (QFN, 48-Leads, Body 7x7mm, Pitch 0.5mm, NSC Recommended)
pins: 1 VA (power), 2 AGND (power), 3 VIN- (in), 4 VIN+ (in), 5 AGND (power), 6 VA (power), 7 PD (in), 8 CLK_SEL/DF (in), 9 VA (power), 10 AGND (power), 11 CLK+ (in), 12 CLK- (in), 13 VD (power), 14 DGND (power), 15 VDR (power), 16 DRGND (power), 17 D0 (out), 18 D1 (out), 19 D2 (out), 20 D3 (out), 21 D4 (out), 22 D5 (out), 23 D6 (out), 24 D7 (out), 25 VDR (power), 26 DRGND (power), 27 D8 (out), 28 D9 (out), 29 D10 (out), 30 D11 (out), 31 D12 (out), 32 D13 (out), 33 OVR (out), 34 DRDY (out), 35 DRGND (power), 36 VDR (power), 37 VA (power), 38 AGND (power), 39 AGND (power), 40 VA (power), 41 VA (power), 42 AGND (power), 43 VRP, 44 VRN, 45 VRM, 46 VREF (power), 47 AGND (power), 48 VA (power), 49 DAP (power)

## ADC14155CISQE
designator U?
14-Bit, 155 MSPS, 1.1 GHz Bandwidth A/D Converter; PartNumber: ADC14155CISQE; Manufacturer: National Semiconductor; CompType: ADC IC; PackageTopMarking: NS*UZXYTT*14155SQE
footprint SQA48A (QFN, 48-Leads, Body 7x7mm, Pitch 0.5mm, NSC Recommended)
pins: 1 VA (power), 2 AGND (power), 3 VIN- (in), 4 VIN+ (in), 5 AGND (power), 6 VA (power), 7 PD (in), 8 CLK_SEL/DF (in), 9 VA (power), 10 AGND (power), 11 CLK+ (in), 12 CLK- (in), 13 VD (power), 14 DGND (power), 15 VDR (power), 16 DRGND (power), 17 D0 (out), 18 D1 (out), 19 D2 (out), 20 D3 (out), 21 D4 (out), 22 D5 (out), 23 D6 (out), 24 D7 (out), 25 VDR (power), 26 DRGND (power), 27 D8 (out), 28 D9 (out), 29 D10 (out), 30 D11 (out), 31 D12 (out), 32 D13 (out), 33 OVR (out), 34 DRDY (out), 35 DRGND (power), 36 VDR (power), 37 VA (power), 38 AGND (power), 39 AGND (power), 40 VA (power), 41 VA (power), 42 AGND (power), 43 VRP, 44 VRN, 45 VRM, 46 VREF (power), 47 AGND (power), 48 VA (power), 49 DAP (power)

## ADC14155W-MLS
designator U?
14-Bit, 155 MSPS, 1.1 GHz Bandwidth A/D Converter; PartNumber: ADC14155W-MLS; Manufacturer: National Semiconductor; CompType: ADC IC; PackageTopMarking: NSZSSXXYYA*ADC14155W*-MLS; PowerWise: N; MilaeroCode: EXX
footprint EL48A_N (CQFP, 48-Leads, Body 11.5x11.5mm; Pitch 0.635mm, Gullwing Leadform, Exposed Pad, IPC Medium Density)
footprint EL48A_L (CQFP, 48-Leads, Body 11.5x11.5mm; Pitch 0.635mm, Gullwing Leadform, Exposed Pad, IPC High Density)
footprint EL48A_M (CQFP, 48-Leads, Body 11.5x11.5mm; Pitch 0.635mm, Gullwing Leadform, Exposed Pad, IPC Low Density)
pins: 1 AGND (power), 2 VA (power), 3 AGND (power), 4 VIN- (in), 5 VIN+ (in), 6 AGND (power), 7 PD (in), 8 CLK_SEL/DF (in), 9 VA (power), 10 AGND (power), 11 CLK+ (in), 12 CLK- (in), 13 VD (power), 14 DGND (power), 15 DRGND (power), 16 VDR (power), 17 D0 (LSB) (out), 18 D1 (out), 19 D2 (out), 20 D3 (out), 21 D4 (out), 22 D5 (out), 23 D6 (out), 24 D7 (out), 25 VDR (power), 26 VDR (power), 27 D8 (out), 28 D9 (out), 29 D10 (out), 30 D11 (out), 31 D12 (out), 32 D13 (MSB) (out), 33 OVR (out), 34 DRDY (out), 35 DRGND (power), 36 VDR (power), 37 VA (power), 38 AGND (power), 39 AGND (power), 40 VA (power), 41 VA (power), 42 VRP (power), 43 VRP, 44 VRN, 45 VRN, 46 VRM (power), 47 VRM (power), 48 VREF (power), 49 DAP (power)

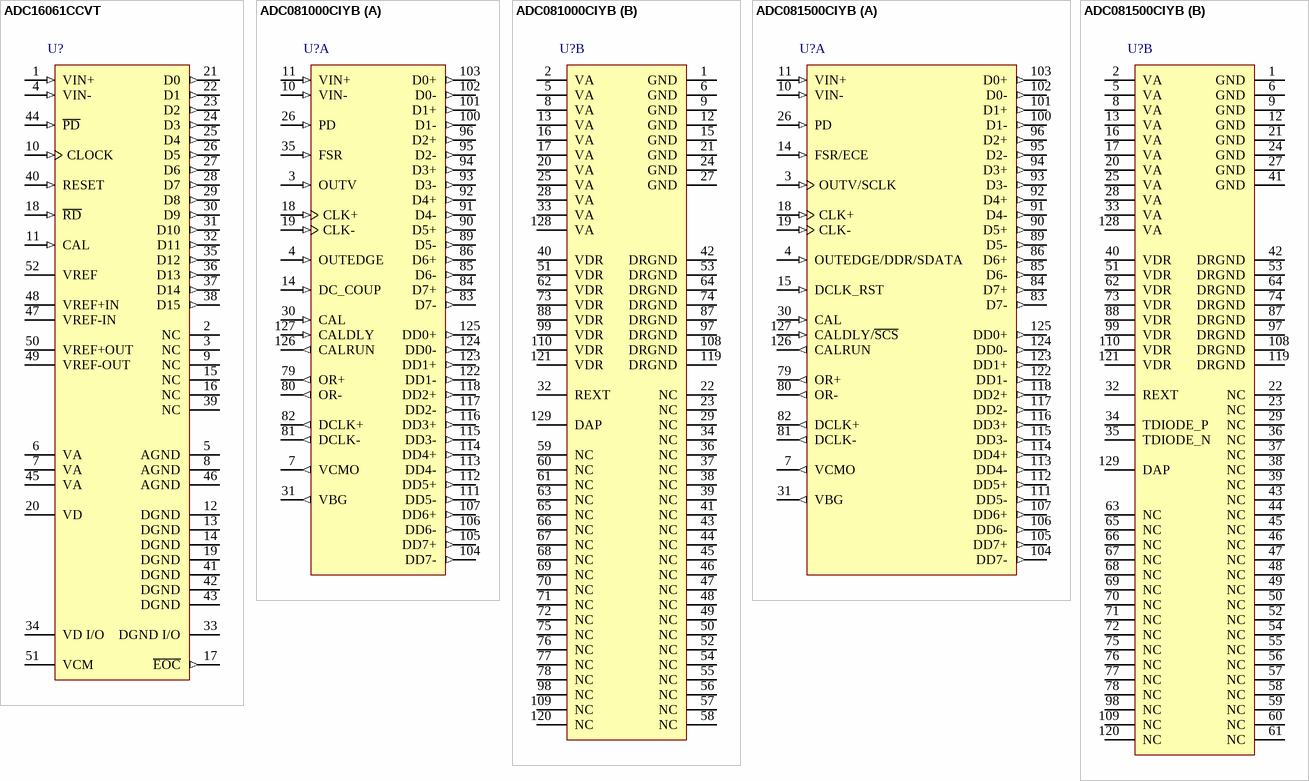
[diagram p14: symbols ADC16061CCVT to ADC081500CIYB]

## ADC16061CCVT
designator U?
Self-Calibrating 16-Bit, 2.5 MSPS, 390 mW A/D Converter; PartNumber: ADC16061CCVT; Manufacturer: National Semiconductor; CompType: ADC IC; PackageTopMarking: NSUZXYYTT*ADC16061*CCVT; PowerWise: N
footprint VEG52A_N (Thin QFP, 52-Leads, Body 10 x 10mm, Pitch 0.65mm, IPC Medium Density)
footprint VEG52A_L (Thin QFP, 52-Leads, Body 10 x 10mm, Pitch 0.65mm, IPC High Density)
footprint VEG52A_M (Thin QFP, 52-Leads, Body 10 x 10mm, Pitch 0.65mm, IPC Low Density)
pins: 1 VIN+ (in), 2 NC, 3 NC, 4 VIN- (in), 5 AGND (power), 6 VA (power), 7 VA (power), 8 AGND (power), 9 NC, 10 CLOCK (in), 11 CAL (in), 12 DGND (power), 13 DGND (power), 14 DGND (power), 15 NC, 16 NC, 17 ~{EOC} (out), 18 ~{RD} (in), 19 DGND (power), 20 VD (power), 21 D0 (out), 22 D1 (out), 23 D2 (out), 24 D3 (out), 25 D4 (out), 26 D5 (out), 27 D6 (out), 28 D7 (out), 29 D8 (out), 30 D9 (out), 31 D10 (out), 32 D11 (out), 33 DGND I/O (power), 34 VD I/O (power), 35 D12 (out), 36 D13 (out), 37 D14 (out), 38 D15 (out), 39 NC, 40 RESET (in), 41 DGND (power), 42 DGND (power), 43 DGND (power), 44 ~{PD} (in), 45 VA (power), 46 AGND (power), 47 VREF-IN (power), 48 VREF+IN (power), 49 VREF-OUT (power), 50 VREF+OUT (power), 51 VCM (power), 52 VREF (power)

## ADC081000CIYB
designator U?
High Performance, Low Power 8-Bit, 1 GSPS A/D Converter; PartNumber: ADC081000CIYB; Manufacturer: National Semiconductor; CompType: ADC IC; PackageTopMarking: NSUZXYYTTE#*ADC081000*CIYB; PowerWise: Y
footprint VNX128A_N (Thin QFP, 128-Leads, Body 20x20mm, Pitch 0.5mm, Exposed Pad, IPC Medium Density)
footprint VNX128A_L (Thin QFP, 128-Leads, Body 20x20mm, Pitch 0.5mm, Exposed Pad, IPC High Density)
footprint VNX128A_M (Thin QFP, 128-Leads, Body 20x20mm, Pitch 0.5mm, Exposed Pad, IPC Low Density)
part A pins: 3 OUTV (in), 4 OUTEDGE (in), 7 VCMO (out), 10 VIN- (in), 11 VIN+ (in), 14 DC_COUP (in), 18 CLK+ (in), 19 CLK- (in), 26 PD (in), 30 CAL (in), 31 VBG (out), 35 FSR (in), 79 OR+ (out), 80 OR- (out), 81 DCLK- (out), 82 DCLK+ (out), 83 D7- (out), 84 D7+ (out), 85 D6- (out), 86 D6+ (out), 89 D5- (out), 90 D5+ (out), 91 D4- (out), 92 D4+ (out), 93 D3- (out), 94 D3+ (out), 95 D2- (out), 96 D2+ (out), 100 D1- (out), 101 D1+ (out), 102 D0- (out), 103 D0+ (out), 104 DD7- (out), 105 DD7+ (out), 106 DD6- (out), 107 DD6+ (out), 111 DD5- (out), 112 DD5+ (out), 113 DD4- (out), 114 DD4+ (out), 115 DD3- (out), 116 DD3+ (out), 117 DD2- (out), 118 DD2+ (out), 122 DD1- (out), 123 DD1+ (out), 124 DD0- (out), 125 DD0+ (out), 126 CALRUN (out), 127 CALDLY (in)
part B pins: 1 GND (power), 2 VA (power), 5 VA (power), 6 GND (power), 8 VA (power), 9 GND (power), 12 GND (power), 13 VA (power), 15 GND (power), 16 VA (power), 17 VA (power), 20 VA (power), 21 GND (power), 22 NC, 23 NC, 24 GND (power), 25 VA (power), 27 GND (power), 28 VA (power), 29 NC, 32 REXT, 33 VA (power), 34 NC, 36 NC, 37 NC, 38 NC, 39 NC, 40 VDR (power), 41 NC, 42 DRGND (power), 43 NC, 44 NC, 45 NC, 46 NC, 47 NC, 48 NC, 49 NC, 50 NC, 51 VDR (power), 52 NC, 53 DRGND (power), 54 NC, 55 NC, 56 NC, 57 NC, 58 NC, 59 NC, 60 NC, 61 NC, 62 VDR (power), 63 NC, 64 DRGND (power), 65 NC, 66 NC, 67 NC, 68 NC, 69 NC, 70 NC, 71 NC, 72 NC, 73 VDR (power), 74 DRGND (power), 75 NC, 76 NC, 77 NC, 78 NC, 87 DRGND (power), 88 VDR (power), 97 DRGND (power), 98 NC, 99 VDR (power), 108 DRGND (power), 109 NC, 110 VDR (power), 119 DRGND (power), 120 NC, 121 VDR (power), 128 VA (power), 129 DAP (power)

## ADC081500CIYB
designator U?
High Performance, Low Power, 8-Bit, 1.5 GSPS A/D Converter; PartNumber: ADC081500CIYB; Manufacturer: National Semiconductor; CompType: ADC IC; PackageTopMarking: NSUZXYYTTE#*ADC081500*CIYB; PowerWise: Y
footprint VNX128A_N (Thin QFP, 128-Leads, Body 20x20mm, Pitch 0.5mm, Exposed Pad, IPC Medium Density)
footprint VNX128A_L (Thin QFP, 128-Leads, Body 20x20mm, Pitch 0.5mm, Exposed Pad, IPC High Density)
footprint VNX128A_M (Thin QFP, 128-Leads, Body 20x20mm, Pitch 0.5mm, Exposed Pad, IPC Low Density)
part A pins: 3 OUTV/SCLK (in), 4 OUTEDGE/DDR/SDATA (in), 7 VCMO (out), 10 VIN- (in), 11 VIN+ (in), 14 FSR/ECE (in), 15 DCLK_RST (in), 18 CLK+ (in), 19 CLK- (in), 26 PD (in), 30 CAL (in), 31 VBG (out), 79 OR+ (out), 80 OR- (out), 81 DCLK- (out), 82 DCLK+ (out), 83 D7- (out), 84 D7+ (out), 85 D6- (out), 86 D6+ (out), 89 D5- (out), 90 D5+ (out), 91 D4- (out), 92 D4+ (out), 93 D3- (out), 94 D3+ (out), 95 D2- (out), 96 D2+ (out), 100 D1- (out), 101 D1+ (out), 102 D0- (out), 103 D0+ (out), 104 DD7- (out), 105 DD7+ (out), 106 DD6- (out), 107 DD6+ (out), 111 DD5- (out), 112 DD5+ (out), 113 DD4- (out), 114 DD4+ (out), 115 DD3- (out), 116 DD3+ (out), 117 DD2- (out), 118 DD2+ (out), 122 DD1- (out), 123 DD1+ (out), 124 DD0- (out), 125 DD0+ (out), 126 CALRUN (out), 127 CALDLY/~{SCS} (in)
part B pins: 1 GND (power), 2 VA (power), 5 VA (power), 6 GND (power), 8 VA (power), 9 GND (power), 12 GND (power), 13 VA (power), 16 VA (power), 17 VA (power), 20 VA (power), 21 GND (power), 22 NC, 23 NC, 24 GND (power), 25 VA (power), 27 GND (power), 28 VA (power), 29 NC, 32 REXT, 33 VA (power), 34 TDIODE_P, 35 TDIODE_N, 36 NC, 37 NC, 38 NC, 39 NC, 40 VDR (power), 41 GND (power), 42 DRGND (power), 43 NC, 44 NC, 45 NC, 46 NC, 47 NC, 48 NC, 49 NC, 50 NC, 51 VDR (power), 52 NC, 53 DRGND (power), 54 NC, 55 NC, 56 NC, 57 NC, 58 NC, 59 NC, 60 NC, 61 NC, 62 VDR (power), 63 NC, 64 DRGND (power), 65 NC, 66 NC, 67 NC, 68 NC, 69 NC, 70 NC, 71 NC, 72 NC, 73 VDR (power), 74 DRGND (power), 75 NC, 76 NC, 77 NC, 78 NC, 87 DRGND (power), 88 VDR (power), 97 DRGND (power), 98 NC, 99 VDR (power), 108 DRGND (power), 109 NC, 110 VDR (power), 119 DRGND (power), 120 NC, 121 VDR (power), 128 VA (power), 129 DAP (power)

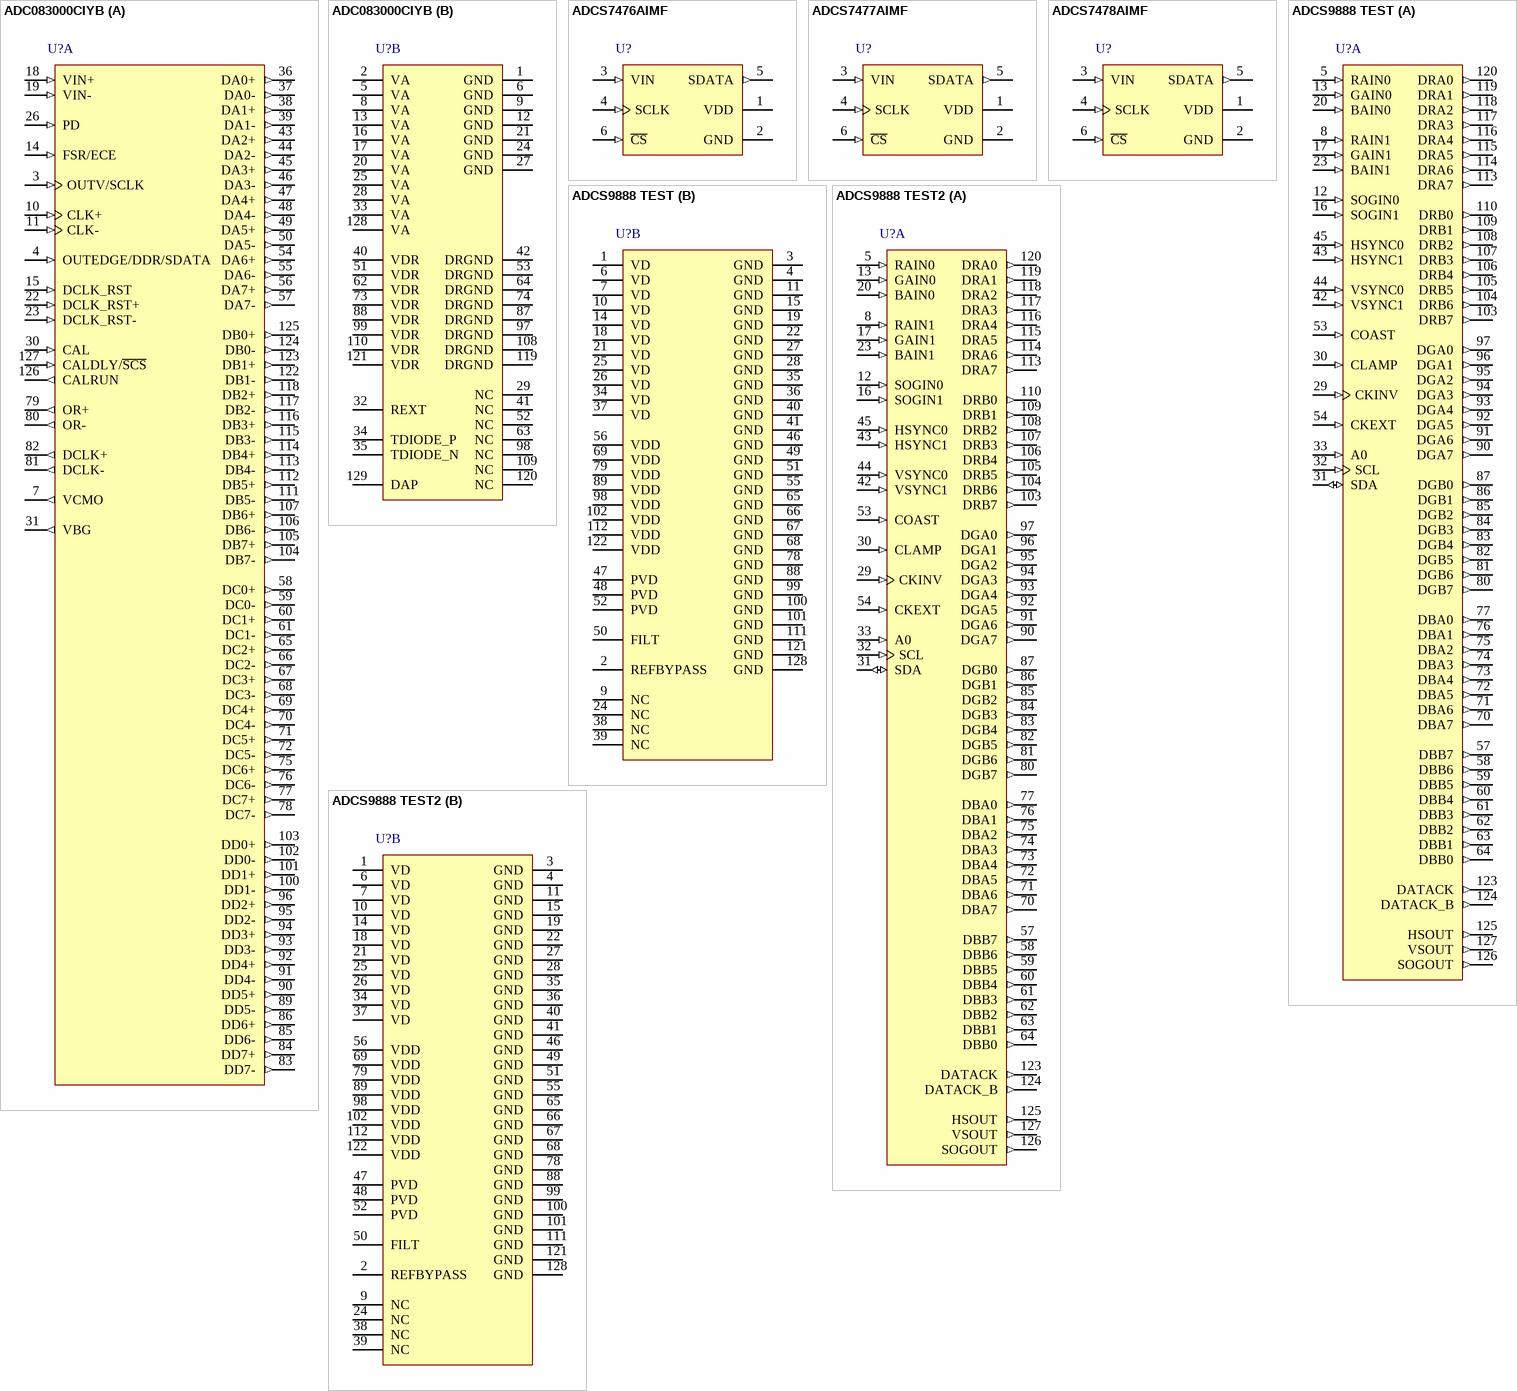
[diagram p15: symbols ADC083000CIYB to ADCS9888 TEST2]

## ADC083000CIYB
designator U?
8-Bit, 3 GSPS, High Performance, Low Power A/D Converter; PartNumber: ADC083000CIYB; Manufacturer: National Semiconductor; CompType: ADC IC; PackageTopMarking: NSUZXYYTTE#*ADC083000CIYB; PowerWise: Y
footprint VNX128A_N (Thin QFP, 128-Leads, Body 20x20mm, Pitch 0.5mm, Exposed Pad, IPC Medium Density)
footprint VNX128A_L (Thin QFP, 128-Leads, Body 20x20mm, Pitch 0.5mm, Exposed Pad, IPC High Density)
footprint VNX128A_M (Thin QFP, 128-Leads, Body 20x20mm, Pitch 0.5mm, Exposed Pad, IPC Low Density)
part A pins: 3 OUTV/SCLK (in), 4 OUTEDGE/DDR/SDATA (in), 7 VCMO (out), 10 CLK+ (in), 11 CLK- (in), 14 FSR/ECE (in), 15 DCLK_RST (in), 18 VIN+ (in), 19 VIN- (in), 22 DCLK_RST+ (in), 23 DCLK_RST- (in), 26 PD (in), 30 CAL (in), 31 VBG (out), 36 DA0+ (out), 37 DA0- (out), 38 DA1+ (out), 39 DA1- (out), 43 DA2+ (out), 44 DA2- (out), 45 DA3+ (out), 46 DA3- (out), 47 DA4+ (out), 48 DA4- (out), 49 DA5+ (out), 50 DA5- (out), 54 DA6+ (out), 55 DA6- (out), 56 DA7+ (out), 57 DA7- (out), 58 DC0+ (out), 59 DC0- (out), 60 DC1+ (out), 61 DC1- (out), 65 DC2+ (out), 66 DC2- (out), 67 DC3+ (out), 68 DC3- (out), 69 DC4+ (out), 70 DC4- (out), 71 DC5+ (out), 72 DC5- (out), 75 DC6+ (out), 76 DC6- (out), 77 DC7+ (out), 78 DC7- (out), 79 OR+ (out), 80 OR- (out), 81 DCLK- (out), 82 DCLK+ (out), 83 DD7- (out), 84 DD7+ (out), 85 DD6- (out), 86 DD6+ (out), 89 DD5- (out), 90 DD5+ (out), 91 DD4- (out), 92 DD4+ (out), 93 DD3- (out), 94 DD3+ (out), 95 DD2- (out), 96 DD2+ (out), 100 DD1- (out), 101 DD1+ (out), 102 DD0- (out), 103 DD0+ (out), 104 DB7- (out), 105 DB7+ (out), 106 DB6- (out), 107 DB6+ (out), 111 DB5- (out), 112 DB5+ (out), 113 DB4- (out), 114 DB4+ (out), 115 DB3- (out), 116 DB3+ (out), 117 DB2- (out), 118 DB2+ (out), 122 DB1- (out), 123 DB1+ (out), 124 DB0- (out), 125 DB0+ (out), 126 CALRUN (out), 127 CALDLY/~{SCS} (in)
part B pins: 1 GND (power), 2 VA (power), 5 VA (power), 6 GND (power), 8 VA (power), 9 GND (power), 12 GND (power), 13 VA (power), 16 VA (power), 17 VA (power), 20 VA (power), 21 GND (power), 24 GND (power), 25 VA (power), 27 GND (power), 28 VA (power), 29 NC, 32 REXT, 33 VA (power), 34 TDIODE_P, 35 TDIODE_N, 40 VDR (power), 41 NC, 42 DRGND (power), 51 VDR (power), 52 NC, 53 DRGND (power), 62 VDR (power), 63 NC, 64 DRGND (power), 73 VDR (power), 74 DRGND (power), 87 DRGND (power), 88 VDR (power), 97 DRGND (power), 98 NC, 99 VDR (power), 108 DRGND (power), 109 NC, 110 VDR (power), 119 DRGND (power), 120 NC, 121 VDR (power), 128 VA (power), 129 DAP (power)

## ADCS7476AIMF
designator U?
1MSPS, 12-/10-/8-Bit A/D Converters in SOT-23 & LLP; PartNumber: ADCS7476AIMF; Manufacturer: National Semiconductor; CompType: ADC IC; PackageTopMarking: X01A*XTT; PowerWise: N
footprint MF06A_N (SOT23, 6-Leads, Body 2.9x1.6mm, Pitch 0.95mm, Lead Span 2.8mm, IPC Medium Density)
footprint MF06A_L (SOT23, 6-Leads, Body 2.9x1.6mm, Pitch 0.95mm, Lead Span 2.8mm, IPC High Density)
footprint MF06A_M (SOT23, 6-Leads, Body 2.9x1.6mm, Pitch 0.95mm, Lead Span 2.8mm, IPC Low Density)
pins: 1 VDD (power), 2 GND (power), 3 VIN (in), 4 SCLK (in), 5 SDATA (out), 6 ~{CS} (in)

## ADCS7477AIMF
designator U?
1MSPS, 12-/10-/8-Bit A/D Converters in SOT-23 & LLP; PartNumber: ADCS7477AIMF; Manufacturer: National Semiconductor; CompType: ADC IC; PackageTopMarking: X02A*XTT; PowerWise: N
footprint MF06A_N (SOT23, 6-Leads, Body 2.9x1.6mm, Pitch 0.95mm, Lead Span 2.8mm, IPC Medium Density)
footprint MF06A_L (SOT23, 6-Leads, Body 2.9x1.6mm, Pitch 0.95mm, Lead Span 2.8mm, IPC High Density)
footprint MF06A_M (SOT23, 6-Leads, Body 2.9x1.6mm, Pitch 0.95mm, Lead Span 2.8mm, IPC Low Density)
pins: 1 VDD (power), 2 GND (power), 3 VIN (in), 4 SCLK (in), 5 SDATA (out), 6 ~{CS} (in)

## ADCS7478AIMF
designator U?
1MSPS, 12-/10-/8-Bit A/D Converters in SOT-23 & LLP; PartNumber: ADCS7478AIMF; Manufacturer: National Semiconductor; CompType: ADC IC; PackageTopMarking: X03A*XTT; PowerWise: N
footprint MF06A_N (SOT23, 6-Leads, Body 2.9x1.6mm, Pitch 0.95mm, Lead Span 2.8mm, IPC Medium Density)
footprint MF06A_L (SOT23, 6-Leads, Body 2.9x1.6mm, Pitch 0.95mm, Lead Span 2.8mm, IPC High Density)
footprint MF06A_M (SOT23, 6-Leads, Body 2.9x1.6mm, Pitch 0.95mm, Lead Span 2.8mm, IPC Low Density)
pins: 1 VDD (power), 2 GND (power), 3 VIN (in), 4 SCLK (in), 5 SDATA (out), 6 ~{CS} (in)

## ADCS9888 TEST
designator U?
205/170/140 MSPS Video Analog Front End; PartNumber: ADCS9888 TEST; Manufacturer: National Semiconductor; CompType: ADC IC; PackageTopMarking: NSUZXYYTTE#*ADCS9888 TEST; PowerWise: N
footprint VLA128A_N (Shrink QFP, 128-Leads, Body 20x14 mm, Pitch 0.5mm, IPC Medium Density)
footprint VLA128A_L (Shrink QFP, 128-Leads, Body 20x14 mm, Pitch 0.5mm, IPC High Density)
footprint VLA128A_M (Shrink QFP, 128-Leads, Body 20x14 mm, Pitch 0.5mm, IPC Low Density)
part A pins: 5 RAIN0 (in), 8 RAIN1 (in), 12 SOGIN0 (in), 13 GAIN0 (in), 16 SOGIN1 (in), 17 GAIN1 (in), 20 BAIN0 (in), 23 BAIN1 (in), 29 CKINV (in), 30 CLAMP (in), 31 SDA (io), 32 SCL (in), 33 A0 (in), 42 VSYNC1 (in), 43 HSYNC1 (in), 44 VSYNC0 (in), 45 HSYNC0 (in), 53 COAST (in), 54 CKEXT (in), 57 DBB7 (out), 58 DBB6 (out), 59 DBB5 (out), 60 DBB4 (out), 61 DBB3 (out), 62 DBB2 (out), 63 DBB1 (out), 64 DBB0 (out), 70 DBA7 (out), 71 DBA6 (out), 72 DBA5 (out), 73 DBA4 (out), 74 DBA3 (out), 75 DBA2 (out), 76 DBA1 (out), 77 DBA0 (out), 80 DGB7 (out), 81 DGB6 (out), 82 DGB5 (out), 83 DGB4 (out), 84 DGB3 (out), 85 DGB2 (out), 86 DGB1 (out), 87 DGB0 (out), 90 DGA7 (out), 91 DGA6 (out), 92 DGA5 (out), 93 DGA4 (out), 94 DGA3 (out), 95 DGA2 (out), 96 DGA1 (out), 97 DGA0 (out), 103 DRB7 (out), 104 DRB6 (out), 105 DRB5 (out), 106 DRB4 (out), 107 DRB3 (out), 108 DRB2 (out), 109 DRB1 (out), 110 DRB0 (out), 113 DRA7 (out), 114 DRA6 (out), 115 DRA5 (out), 116 DRA4 (out), 117 DRA3 (out), 118 DRA2 (out), 119 DRA1 (out), 120 DRA0 (out), 123 DATACK (out), 124 DATACK_B (out), 125 HSOUT (out), 126 SOGOUT (out), 127 VSOUT (out)
part B pins: 1 VD (power), 2 REFBYPASS, 3 GND (power), 4 GND (power), 6 VD (power), 7 VD (power), 9 NC, 10 VD (power), 11 GND (power), 14 VD (power), 15 GND (power), 18 VD (power), 19 GND (power), 21 VD (power), 22 GND (power), 24 NC, 25 VD (power), 26 VD (power), 27 GND (power), 28 GND (power), 34 VD (power), 35 GND (power), 36 GND (power), 37 VD (power), 38 NC, 39 NC, 40 GND (power), 41 GND (power), 46 GND (power), 47 PVD (power), 48 PVD (power), 49 GND (power), 50 FILT, 51 GND (power), 52 PVD (power), 55 GND (power), 56 VDD (power), 65 GND (power), 66 GND (power), 67 GND (power), 68 GND (power), 69 VDD (power), 78 GND (power), 79 VDD (power), 88 GND (power), 89 VDD (power), 98 VDD (power), 99 GND (power), 100 GND (power), 101 GND (power), 102 VDD (power), 111 GND (power), 112 VDD (power), 121 GND (power), 122 VDD (power), 128 GND (power)

## ADCS9888 TEST2
designator U?
205/170/140 MSPS Video Analog Front End; PartNumber: ADCS9888 TEST2; Manufacturer: National Semiconductor; CompType: ADC IC; PackageTopMarking: NSUZXYYTTE#*ADCS9888 TEST2; PowerWise: N
footprint VLA128A_N (Shrink QFP, 128-Leads, Body 20x14 mm, Pitch 0.5mm, IPC Medium Density)
footprint VLA128A_L (Shrink QFP, 128-Leads, Body 20x14 mm, Pitch 0.5mm, IPC High Density)
footprint VLA128A_M (Shrink QFP, 128-Leads, Body 20x14 mm, Pitch 0.5mm, IPC Low Density)
part A pins: 5 RAIN0 (in), 8 RAIN1 (in), 12 SOGIN0 (in), 13 GAIN0 (in), 16 SOGIN1 (in), 17 GAIN1 (in), 20 BAIN0 (in), 23 BAIN1 (in), 29 CKINV (in), 30 CLAMP (in), 31 SDA (io), 32 SCL (in), 33 A0 (in), 42 VSYNC1 (in), 43 HSYNC1 (in), 44 VSYNC0 (in), 45 HSYNC0 (in), 53 COAST (in), 54 CKEXT (in), 57 DBB7 (out), 58 DBB6 (out), 59 DBB5 (out), 60 DBB4 (out), 61 DBB3 (out), 62 DBB2 (out), 63 DBB1 (out), 64 DBB0 (out), 70 DBA7 (out), 71 DBA6 (out), 72 DBA5 (out), 73 DBA4 (out), 74 DBA3 (out), 75 DBA2 (out), 76 DBA1 (out), 77 DBA0 (out), 80 DGB7 (out), 81 DGB6 (out), 82 DGB5 (out), 83 DGB4 (out), 84 DGB3 (out), 85 DGB2 (out), 86 DGB1 (out), 87 DGB0 (out), 90 DGA7 (out), 91 DGA6 (out), 92 DGA5 (out), 93 DGA4 (out), 94 DGA3 (out), 95 DGA2 (out), 96 DGA1 (out), 97 DGA0 (out), 103 DRB7 (out), 104 DRB6 (out), 105 DRB5 (out), 106 DRB4 (out), 107 DRB3 (out), 108 DRB2 (out), 109 DRB1 (out), 110 DRB0 (out), 113 DRA7 (out), 114 DRA6 (out), 115 DRA5 (out), 116 DRA4 (out), 117 DRA3 (out), 118 DRA2 (out), 119 DRA1 (out), 120 DRA0 (out), 123 DATACK (out), 124 DATACK_B (out), 125 HSOUT (out), 126 SOGOUT (out), 127 VSOUT (out)
part B pins: 1 VD (power), 2 REFBYPASS, 3 GND (power), 4 GND (power), 6 VD (power), 7 VD (power), 9 NC, 10 VD (power), 11 GND (power), 14 VD (power), 15 GND (power), 18 VD (power), 19 GND (power), 21 VD (power), 22 GND (power), 24 NC, 25 VD (power), 26 VD (power), 27 GND (power), 28 GND (power), 34 VD (power), 35 GND (power), 36 GND (power), 37 VD (power), 38 NC, 39 NC, 40 GND (power), 41 GND (power), 46 GND (power), 47 PVD (power), 48 PVD (power), 49 GND (power), 50 FILT, 51 GND (power), 52 PVD (power), 55 GND (power), 56 VDD (power), 65 GND (power), 66 GND (power), 67 GND (power), 68 GND (power), 69 VDD (power), 78 GND (power), 79 VDD (power), 88 GND (power), 89 VDD (power), 98 VDD (power), 99 GND (power), 100 GND (power), 101 GND (power), 102 VDD (power), 111 GND (power), 112 VDD (power), 121 GND (power), 122 VDD (power), 128 GND (power)

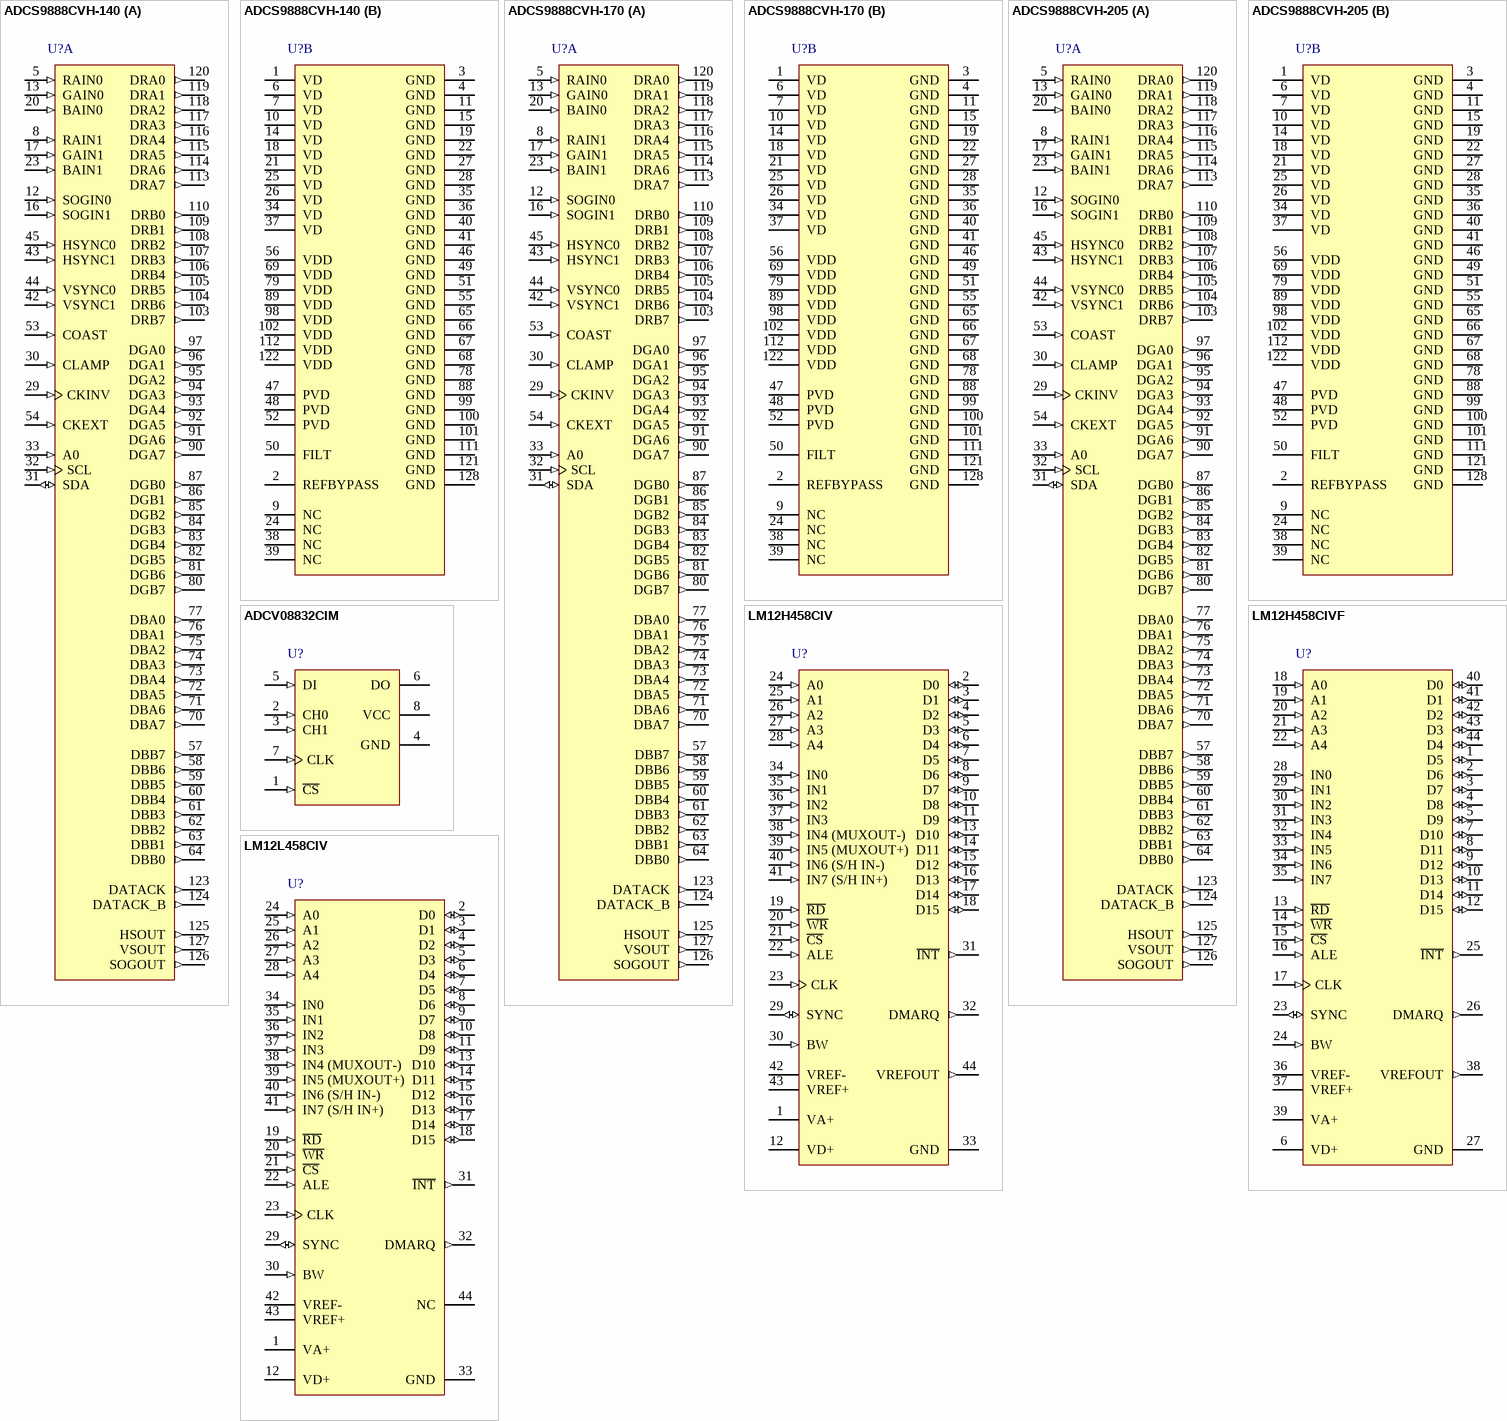
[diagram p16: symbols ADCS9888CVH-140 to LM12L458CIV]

## ADCS9888CVH-140
designator U?
205/170/140 MSPS Video Analog Front End; PartNumber: ADCS9888CVH-140; Manufacturer: National Semiconductor; CompType: ADC IC; PackageTopMarking: NSUZXYYTTE#*ADCS9888CVH*-140
footprint VLA128A_N (Shrink QFP, 128-Leads, Body 20x14 mm, Pitch 0.5mm, IPC Medium Density)
footprint VLA128A_L (Shrink QFP, 128-Leads, Body 20x14 mm, Pitch 0.5mm, IPC High Density)
footprint VLA128A_M (Shrink QFP, 128-Leads, Body 20x14 mm, Pitch 0.5mm, IPC Low Density)
part A pins: 5 RAIN0 (in), 8 RAIN1 (in), 12 SOGIN0 (in), 13 GAIN0 (in), 16 SOGIN1 (in), 17 GAIN1 (in), 20 BAIN0 (in), 23 BAIN1 (in), 29 CKINV (in), 30 CLAMP (in), 31 SDA (io), 32 SCL (in), 33 A0 (in), 42 VSYNC1 (in), 43 HSYNC1 (in), 44 VSYNC0 (in), 45 HSYNC0 (in), 53 COAST (in), 54 CKEXT (in), 57 DBB7 (out), 58 DBB6 (out), 59 DBB5 (out), 60 DBB4 (out), 61 DBB3 (out), 62 DBB2 (out), 63 DBB1 (out), 64 DBB0 (out), 70 DBA7 (out), 71 DBA6 (out), 72 DBA5 (out), 73 DBA4 (out), 74 DBA3 (out), 75 DBA2 (out), 76 DBA1 (out), 77 DBA0 (out), 80 DGB7 (out), 81 DGB6 (out), 82 DGB5 (out), 83 DGB4 (out), 84 DGB3 (out), 85 DGB2 (out), 86 DGB1 (out), 87 DGB0 (out), 90 DGA7 (out), 91 DGA6 (out), 92 DGA5 (out), 93 DGA4 (out), 94 DGA3 (out), 95 DGA2 (out), 96 DGA1 (out), 97 DGA0 (out), 103 DRB7 (out), 104 DRB6 (out), 105 DRB5 (out), 106 DRB4 (out), 107 DRB3 (out), 108 DRB2 (out), 109 DRB1 (out), 110 DRB0 (out), 113 DRA7 (out), 114 DRA6 (out), 115 DRA5 (out), 116 DRA4 (out), 117 DRA3 (out), 118 DRA2 (out), 119 DRA1 (out), 120 DRA0 (out), 123 DATACK (out), 124 DATACK_B (out), 125 HSOUT (out), 126 SOGOUT (out), 127 VSOUT (out)
part B pins: 1 VD (power), 2 REFBYPASS, 3 GND (power), 4 GND (power), 6 VD (power), 7 VD (power), 9 NC, 10 VD (power), 11 GND (power), 14 VD (power), 15 GND (power), 18 VD (power), 19 GND (power), 21 VD (power), 22 GND (power), 24 NC, 25 VD (power), 26 VD (power), 27 GND (power), 28 GND (power), 34 VD (power), 35 GND (power), 36 GND (power), 37 VD (power), 38 NC, 39 NC, 40 GND (power), 41 GND (power), 46 GND (power), 47 PVD (power), 48 PVD (power), 49 GND (power), 50 FILT, 51 GND (power), 52 PVD (power), 55 GND (power), 56 VDD (power), 65 GND (power), 66 GND (power), 67 GND (power), 68 GND (power), 69 VDD (power), 78 GND (power), 79 VDD (power), 88 GND (power), 89 VDD (power), 98 VDD (power), 99 GND (power), 100 GND (power), 101 GND (power), 102 VDD (power), 111 GND (power), 112 VDD (power), 121 GND (power), 122 VDD (power), 128 GND (power)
